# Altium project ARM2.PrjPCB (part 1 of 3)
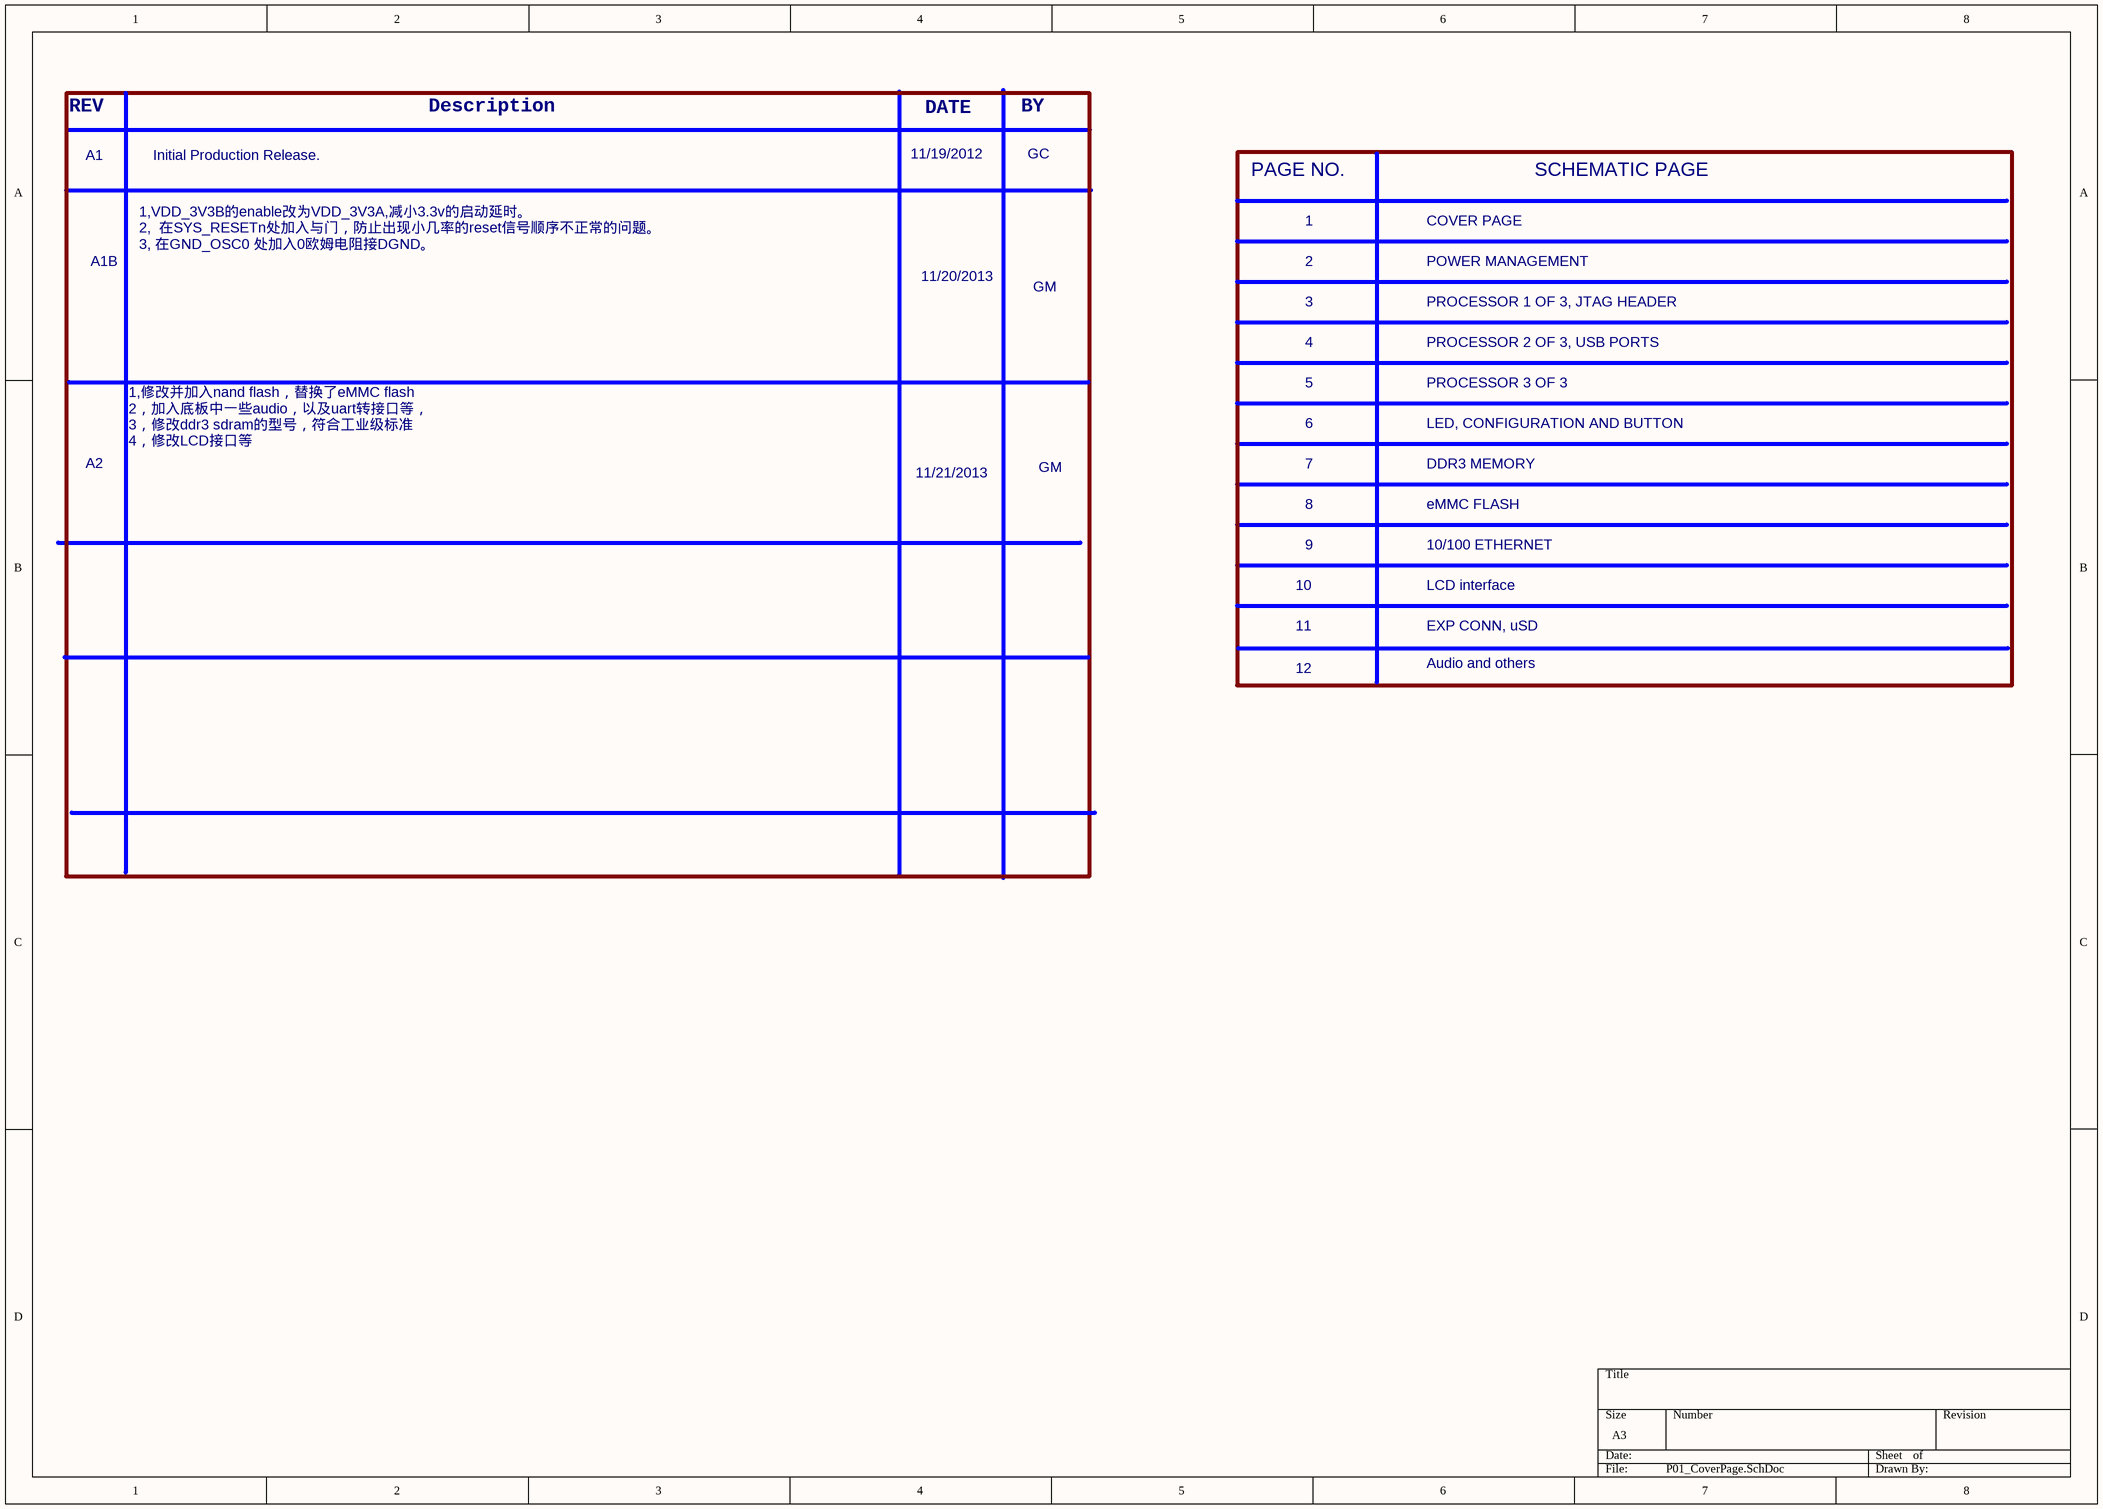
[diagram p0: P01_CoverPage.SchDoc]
12 sheets, 679 parts. Net scope: global (net labels, ports and power ports of the same name join across sheets).
Board file: ARM2.PcbDoc
Sheets:
  P01_CoverPage.SchDoc
  P02_PowerManagement.SchDoc
  P03_Processor1_3.SchDoc
  P04_Processor2_3.SchDoc
  P05_Processor3_3.SchDoc
  P06_LED_BootConfig.SchDoc
  P07_DDR3_SDRAM.SchDoc
  P08_NandFlash.SchDoc
  P09_Ethernet.SchDoc
  P10_LCD.SchDoc
  P11_SDcard.SchDoc
  P12_Exp_Audio.SchDoc

## Sheet P01_CoverPage.SchDoc
size A3

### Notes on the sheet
- REV
- Description
- DATE
- BY
- A1
- Initial Production Release.
- 11/19/2012
- GC
- PAGE NO.
- SCHEMATIC PAGE
- 1
- COVER PAGE
- A1B
- 11/20/2013
- GM
- 3
- 2
- PROCESSOR 1 OF 3, JTAG HEADER
- POWER MANAGEMENT
- 1,VDD_3V3B的enable改为VDD_3V3A,减小3.3v的启动延时。
  2,  在SYS_RESETn处加入与门，防止出现小几率的reset信号顺序不正常的问题。
  3, 在GND_OSC0 处加入0欧姆电阻接DGND。
- 4
- PROCESSOR 2 OF 3, USB PORTS
- 5
- 6
- LED, CONFIGURATION AND BUTTON
- PROCESSOR 3 OF 3
- A2
- 11/21/2013
- 8
- 7
- eMMC FLASH
- DDR3 MEMORY
- 1,修改并加入nand flash，替换了eMMC flash
  2，加入底板中一些audio，以及uart转接口等，
  3，修改ddr3 sdram的型号，符合工业级标准
  4，修改LCD接口等
- 9
- 10/100 ETHERNET
- 10
- 11
- LCD interface
- EXP CONN, uSD
- 12
- Audio and others

## Sheet P02_PowerManagement.SchDoc
size A3
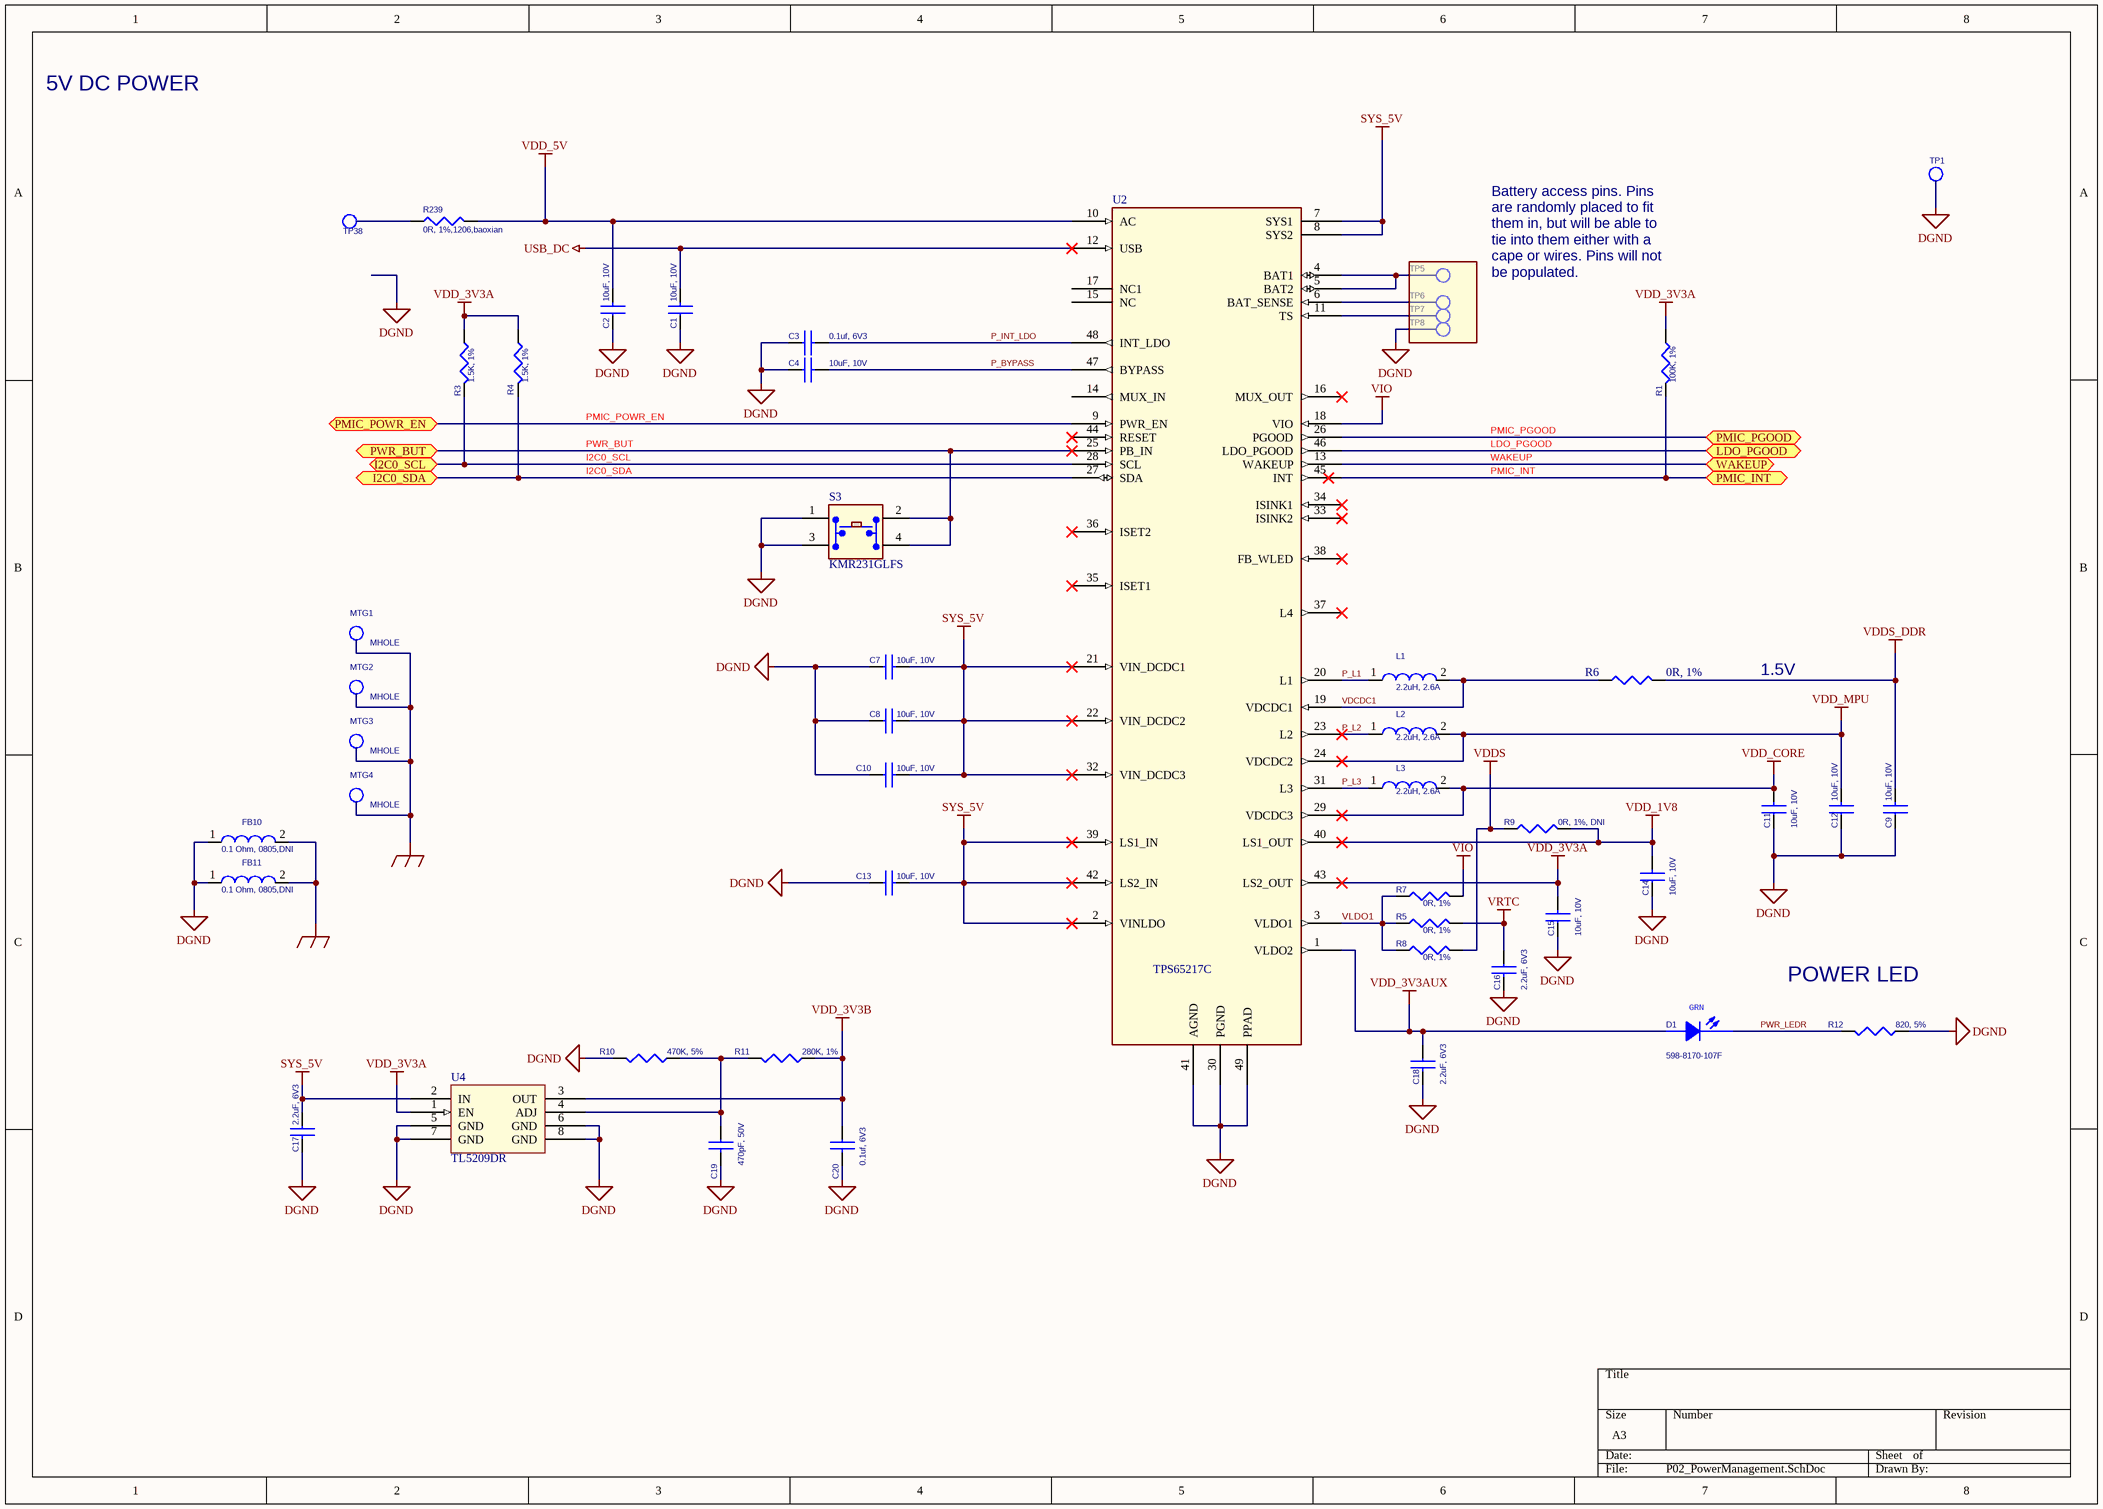
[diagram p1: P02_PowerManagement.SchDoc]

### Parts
C1  10uF, 10V  [805]
C2  10uF, 10V  [805]
C3  0.1uf, 6V3  [402]
C4  10uF, 10V  [805]
C7  10uF, 10V  [805]
C8  10uF, 10V  [805]
C9  10uF, 10V  [805]
C10  10uF, 10V  [805]
C11  10uF, 10V  [805]
C12  10uF, 10V  [805]
C13  10uF, 10V  [805]
C14  10uF, 10V  [805]
C15  10uF, 10V  [805]
C16  2.2uF, 6V3  [0805]
C17  2.2uF, 6V3  [0805]
C18  2.2uF, 6V3  [0805]
C19  470pF, 50V  [402]
C20  0.1uf, 6V3  [402]
D1  598-8170-107F  [LED_0603]
FB10  0.1 Ohm, 0805,DNI  [SM-7351-IND-0805]
FB11  0.1 Ohm, 0805,DNI  [SM-7351-IND-0805]
L1  2.2uH, 2.6A  [2520]
L2  2.2uH, 2.6A  [2520]
L3  2.2uH, 2.6A  [2520]
MTG1  MHOLE  [MTGH200C125D_PL]  (no BOM)
MTG2  MHOLE  [MTGH200C125D_PL]  (no BOM)
MTG3  MHOLE  [MTGH200C125D_PL]  (no BOM)
MTG4  MHOLE  [MTGH200C125D_PL]  (no BOM)
R1  100K, 1%  [R0402]
R3  1.5K, 1%  [R0402]
R4  1.5K, 1%  [R0402]
R5  0R, 1%  [R0402]
R6  0R, 1%  [R0402]
R7  0R, 1%  [R0402]
R8  0R, 1%  [R0402]
R9  0R, 1%, DNI  [R0402]
R10  470K, 5%  [R0402]
R11  280K, 1%  [R0402]
R12  820, 5%  [R0402]
R239  0R, 1%,1206,baoxian  [R1206]
S3  KMR231GLFS  [SW4SMD_63X161LS]
TP1  TESTPT1  [tp1-8040]  (value not drawn)  (no BOM)
TP5  TESTPT1  [TP60C33D]  (value not drawn)  (no BOM)
TP6  TESTPT1  [TP60C33D]  (value not drawn)  (no BOM)
TP7  TESTPT1  [TP60C33D]  (value not drawn)  (no BOM)
TP8  TESTPT1  [TP60C33D]  (value not drawn)  (no BOM)
TP38  TESTPT1  [tp1-8040]  (value not drawn)  (no BOM)
U2  TPS65217C  [U_48_RSL/TPS65217CRSL/RSL]
U4  TL5209DR  [SO8-25X75/TL5209DR/8-SOIC]

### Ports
I2C0_SCL, I2C0_SDA, LDO_PGOOD, PMIC_INT, PMIC_PGOOD, PMIC_POWR_EN, PWR_BUT, WAKEUP

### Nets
DGND: C1.1 C2.1 C3.1 C4.1 C7.1 C8.1 C9.1 C10.1 C11.1 C12.1 C13.1 C14.1 C15.1 C16.2 C17.2 C18.2 C19.2 C20.2 FB10.1 FB11.1 R10.2 R12.1 S3.1(A1) S3.3(A3) TP1.1(TP) TP8.1(TP) U2.30(PGND) U2.41(AGND) U2.49(PPAD) U4.5(GND) U4.6(GND) U4.7(GND) U4.8(GND)
GND_EARTH: FB10.2 FB11.2 MTG1.1(TP) MTG2.1(TP) MTG3.1(TP) MTG4.1(TP)
SYS_5V: C7.2 C8.2 C10.2 C13.2 C17.1 U2.2(VINLDO) U2.7(SYS1) U2.8(SYS2) U2.21(VIN_DCDC1) U2.22(VIN_DCDC2) U2.32(VIN_DCDC3) U2.39(LS1_IN) U2.42(LS2_IN) U4.2(IN)
USB_DC: C1.2 U2.12(USB)
VDD_1V8: C14.2 R9.2 U2.40(LS1_OUT)
VDD_3V3A: C15.2 R1.1 R3.1 R4.1 U2.43(LS2_OUT) U4.1(EN)
VDD_3V3AUX: C18.1 D1.2(A) U2.1(VLDO2)
VDD_3V3B: C20.1 R11.1 U4.3(OUT)
VDD_5V: C2.2 R239.2 U2.10(AC)
VDD_CORE: C11.2 L3.2 U2.29(VDCDC3)
VDD_MPU: C12.2 L2.2 U2.24(VDCDC2)
VDDS: R8.2 R9.1
VDDS_DDR: C9.2 R6.2
VIO: R7.2 U2.18(VIO)
VRTC: C16.1 R5.2
I2C0_SCL: R3.2 U2.28(SCL) ; port I2C0_SCL
I2C0_SDA: R4.2 U2.27(SDA) ; port I2C0_SDA
LDO_PGOOD: U2.46(LDO_PGOOD) ; port LDO_PGOOD
P_BYPASS: C4.2 U2.47(BYPASS)
P_INT_LDO: C3.2 U2.48(INT_LDO)
P_L1: L1.1 U2.20(L1)
P_L2: L2.1 U2.23(L2)
P_L3: L3.1 U2.31(L3)
PMIC_INT: R1.2 U2.45(INT) ; port PMIC_INT
PMIC_PGOOD: U2.26(PGOOD) ; port PMIC_PGOOD
PMIC_POWR_EN: U2.9(PWR_EN) ; port PMIC_POWR_EN
PWR_BUT: S3.2(A2) S3.4 U2.25(PB_IN) ; port PWR_BUT
PWR_LEDR: D1.1(C) R12.2
VDCDC1: L1.2 R6.1 U2.19(VDCDC1)
VLDO1: R5.1 R7.1 R8.1 U2.3(VLDO1)
WAKEUP: U2.13(WAKEUP) ; port WAKEUP
NetC19_1: C19.1 R10.1 R11.2 U4.4(ADJ)
NetR239_1: R239.1 TP38.1(TP)
NetTP5_1: TP5.1(TP) U2.4(BAT1) U2.5(BAT2)
NetTP6_1: TP6.1(TP) U2.6(BAT_SENSE)
NetTP7_1: TP7.1(TP) U2.11(TS)

Not connected (* = marked no-connect by the designer): U2 14(MUX_IN) 15(NC) 16(MUX_OUT)* 17(NC1) 33(ISINK2)* 34(ISINK1)* 35(ISET1)* 36(ISET2)* 37(L4)* 38(FB_WLED)* 44(RESET)*

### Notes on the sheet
- 5V DC POWER
- Battery access pins. Pins are randomly placed to fit them in, but will be able to tie into them either with a cape or wires. Pins will not be populated.
- 1.5V
- (near R12) POWER LED

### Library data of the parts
C1 C2 = CAP_4.7uF_X5R_6.3V_10%_0603: CAP CER 10UF 10V Y5V 0805; Manufacturer: TDK Corporation; Manufacturer Part Number: C2012Y5V1A106Z; Capacitance: 10µF; Tolerance: -20%, +80%; Temperature Coefficient: Y5V (F)
C3 = CAP_10uF_Y5V_10V_10%_0805: CAP CER 0.1UF 6.3V 10% X5R 0402; Manufacturer: TDK Corporation; Manufacturer Part Number: C1005X5R0J104K050BA; Capacitance: 0.1µF; Tolerance: ?0%
C4 C7-C15 = CAP_10uF_Y5V_10V_10%_0805: CAP CER 10UF 10V Y5V 0805; Manufacturer: TDK Corporation; Manufacturer Part Number: C2012Y5V1A106Z; Capacitance: 10µF; Tolerance: -20%, +80%; Temperature Coefficient: Y5V (F)
C16-C18 = CAP_2.2uF_X5R_6.3V_10%_0402: CAP CER 2.2UF 6.3V 10% X5R 0402; Manufacturer: TDK Corporation; Manufacturer Part Number: C1005X5R0J225K050BC; Capacitance: 2.2µF; Tolerance: ?0%
C19 = CAP_2.2uF_X5R_6.3V_10%_0402: CAP CER 470PF 50V 10% X7R 0402; Manufacturer: Murata Electronics North America; Manufacturer Part Number: GRM155R71H471KA01D; Tolerance: ?0%
C20 = CAP_0.1uF_X7R_16V_10% 0402: CAP CER 0.1UF 6.3V 10% X5R 0402; Manufacturer: TDK Corporation; Manufacturer Part Number: C1005X5R0J104K050BA; Capacitance: 0.1µF; Tolerance: ?0%
D1 = LED_LTST-C150GKT: LED GREEN CLEAR 0805 SMD; Manufacturer: Lite-On Inc; Manufacturer Part Number: LTST-C170KGKT; CLASS: DISCRETE; TN: 257-0020-000; Millicandela Rating: 35mcd; Voltage - Forward (Vf) Typ: 2V; Current - Test: 20mA; Wavelength - Dominant: 571nm; Wavelength - Peak: 574nm; Viewing Angle: 130; Lens Style/Size: Rectangle with Flat Top, 1.4mm x 1.25mm
FB10 FB11 = FER_180_200_0: RES .10 OHM 1/8W 5% 0805; Manufacturer: CTS Resistor Products; Manufacturer Part Number: 73L3R10J; Resistance (Ohms): 0.1; Power (Watts): 0.125W, 1/8W; Temperature Coefficient: ?00ppm/°C; Tolerance: ?%
L1 = IND_2.2uH_2.6A_10%_SMD: Inductor 2.2uH smt 2.6A, 58 milliohm; Manufacturer: Murata Electronics North America; Manufacturer Part Number: LQM2HPN2R2MG0L; Inductance: 2.2µH; Current Rating: 1.3A; Tolerance: ?0%; Shielding: Shielded; DC Resistance (DCR): 100 mOhm Max; Frequency - Self Resonant: 40MHz; Frequency - Test: 1MHz
L2 L3 = IND_2.2uH_2.6A_10%_SMD: INDUCTOR 2.2UH 20% 1300MA 1008; PartName: 2.2uH10%2.6Asmd; Mfr: TDK; MfrNum: VLCF5020T-2R2N2R6-3; TIIntPartnumber: 1L0025; Manufacturer: Murata Electronics North America; Manufacturer Part Number: LQM2HPN2R2MG0L; Vendor: Digikey; Cost100: 1.11; Cost10K: 0.37; Inductance: 2.2µH; Current Rating: 1.3A; Tolerance: ?0%; Shielding: Shielded; DC Resistance (DCR): 100 mOhm Max; Frequency - Self Resonant: 40MHz; Frequency - Test: 1MHz
R1 = RES_100K_1/16W_1%_0402: RES 100K OHM 1/16W 1% 0402 SMD; Manufacturer: Stackpole Electronics Inc; Manufacturer Part Number: RMCF0402FT100K; Power (Watts): 0.063W, 1/16W; Temperature Coefficient: ?00ppm/°C; Tolerance: ?%
R3 R4 = RES_1.5K_1/16W_5%_0402: RES 1.50K OHM 1/16W 1% 0402 SMD; Manufacturer: Yageo; Manufacturer Part Number: RC0402FR-071K5L; Power (Watts): 0.063W, 1/16W; Temperature Coefficient: ?00ppm/°C; Tolerance: ?%
R5-R9 = RES_0_1/16W_1%_0402: RES 0.0 OHM 1/16W 0402 SMD; Manufacturer: Yageo; Manufacturer Part Number: RC0402JR-070RL; Power (Watts): 0.063W, 1/16W; Resistance (Ohms): 0.0; Tolerance: Jumper
R10 R239 = RES_470_1/10W_5%_0402: RES 470K OHM 1/16W 1% 0402 SMD; Manufacturer: Yageo; Manufacturer Part Number: RC0402FR-07470KL; Power (Watts): 0.063W, 1/16W; Temperature Coefficient: ?00ppm/°C; Tolerance: ?%
R11 = RES_470_1/10W_5%_0402: RES 280K OHM 1/16W 1% 0402 SMD; Manufacturer: Stackpole Electronics Inc; Manufacturer Part Number: RMCF0402FT280K; Power (Watts): 0.063W, 1/16W; Temperature Coefficient: ?00ppm/°C; Tolerance: ?%
R12 = RES_470_1/10W_5%_0402: RES 820 OHM 1/10W 5% 0402 SMD; Manufacturer: Yageo; Manufacturer Part Number: RC0402JR-07820RL; Description: RES 820 OHM 1/16W 5% 0402 SMD; Resistance (Ohms): 820; Power (Watts): 0.063W, 1/16W; Temperature Coefficient: ?00ppm/°C; Tolerance: ?%
S3 = KMR2: Microminiature Tact Switch for SMT; Manufacturer: C&K Components; Circuit: SPST-NO; Switch Function: Off-Mom; Contact Rating @ Voltage: 0.05A @ 32VDC; Actuator Type: Standard; Actuator Height off PCB, from Pins: 1.90mm; Actuator Orientation: Top Actuated; Outline: 4.60mm x 2.80mm; Illumination: Non-Illuminated; Operating Force: 300gf; Switch Travel: 0.25mm; Mechanical Life: 150,000 Cycles
U2 = PWR_TPS65217_2: IC PMIC BATT PWR SYST 48VQFN; Manufacturer: Texas Instruments; Manufacturer Part Number: TPS65217CRSLR; Voltage - Supply: 2.75 V ~ 5.8 V
U4 = TL5209: IC LDO VOLT REG 500MA 8-SOIC; Manufacturer: Texas Instruments; Regulator Topology: Positive Adjustable; Voltage - Output: 2.5 V ~ 6.5 V; Voltage - Input: 2.5 V ~ 16 V; Voltage - Dropout (Typical): 0.35V @ 500mA; Number of Regulators: 1; Current - Output: 500mA (Max)

## Sheet P03_Processor1_3.SchDoc
size A2
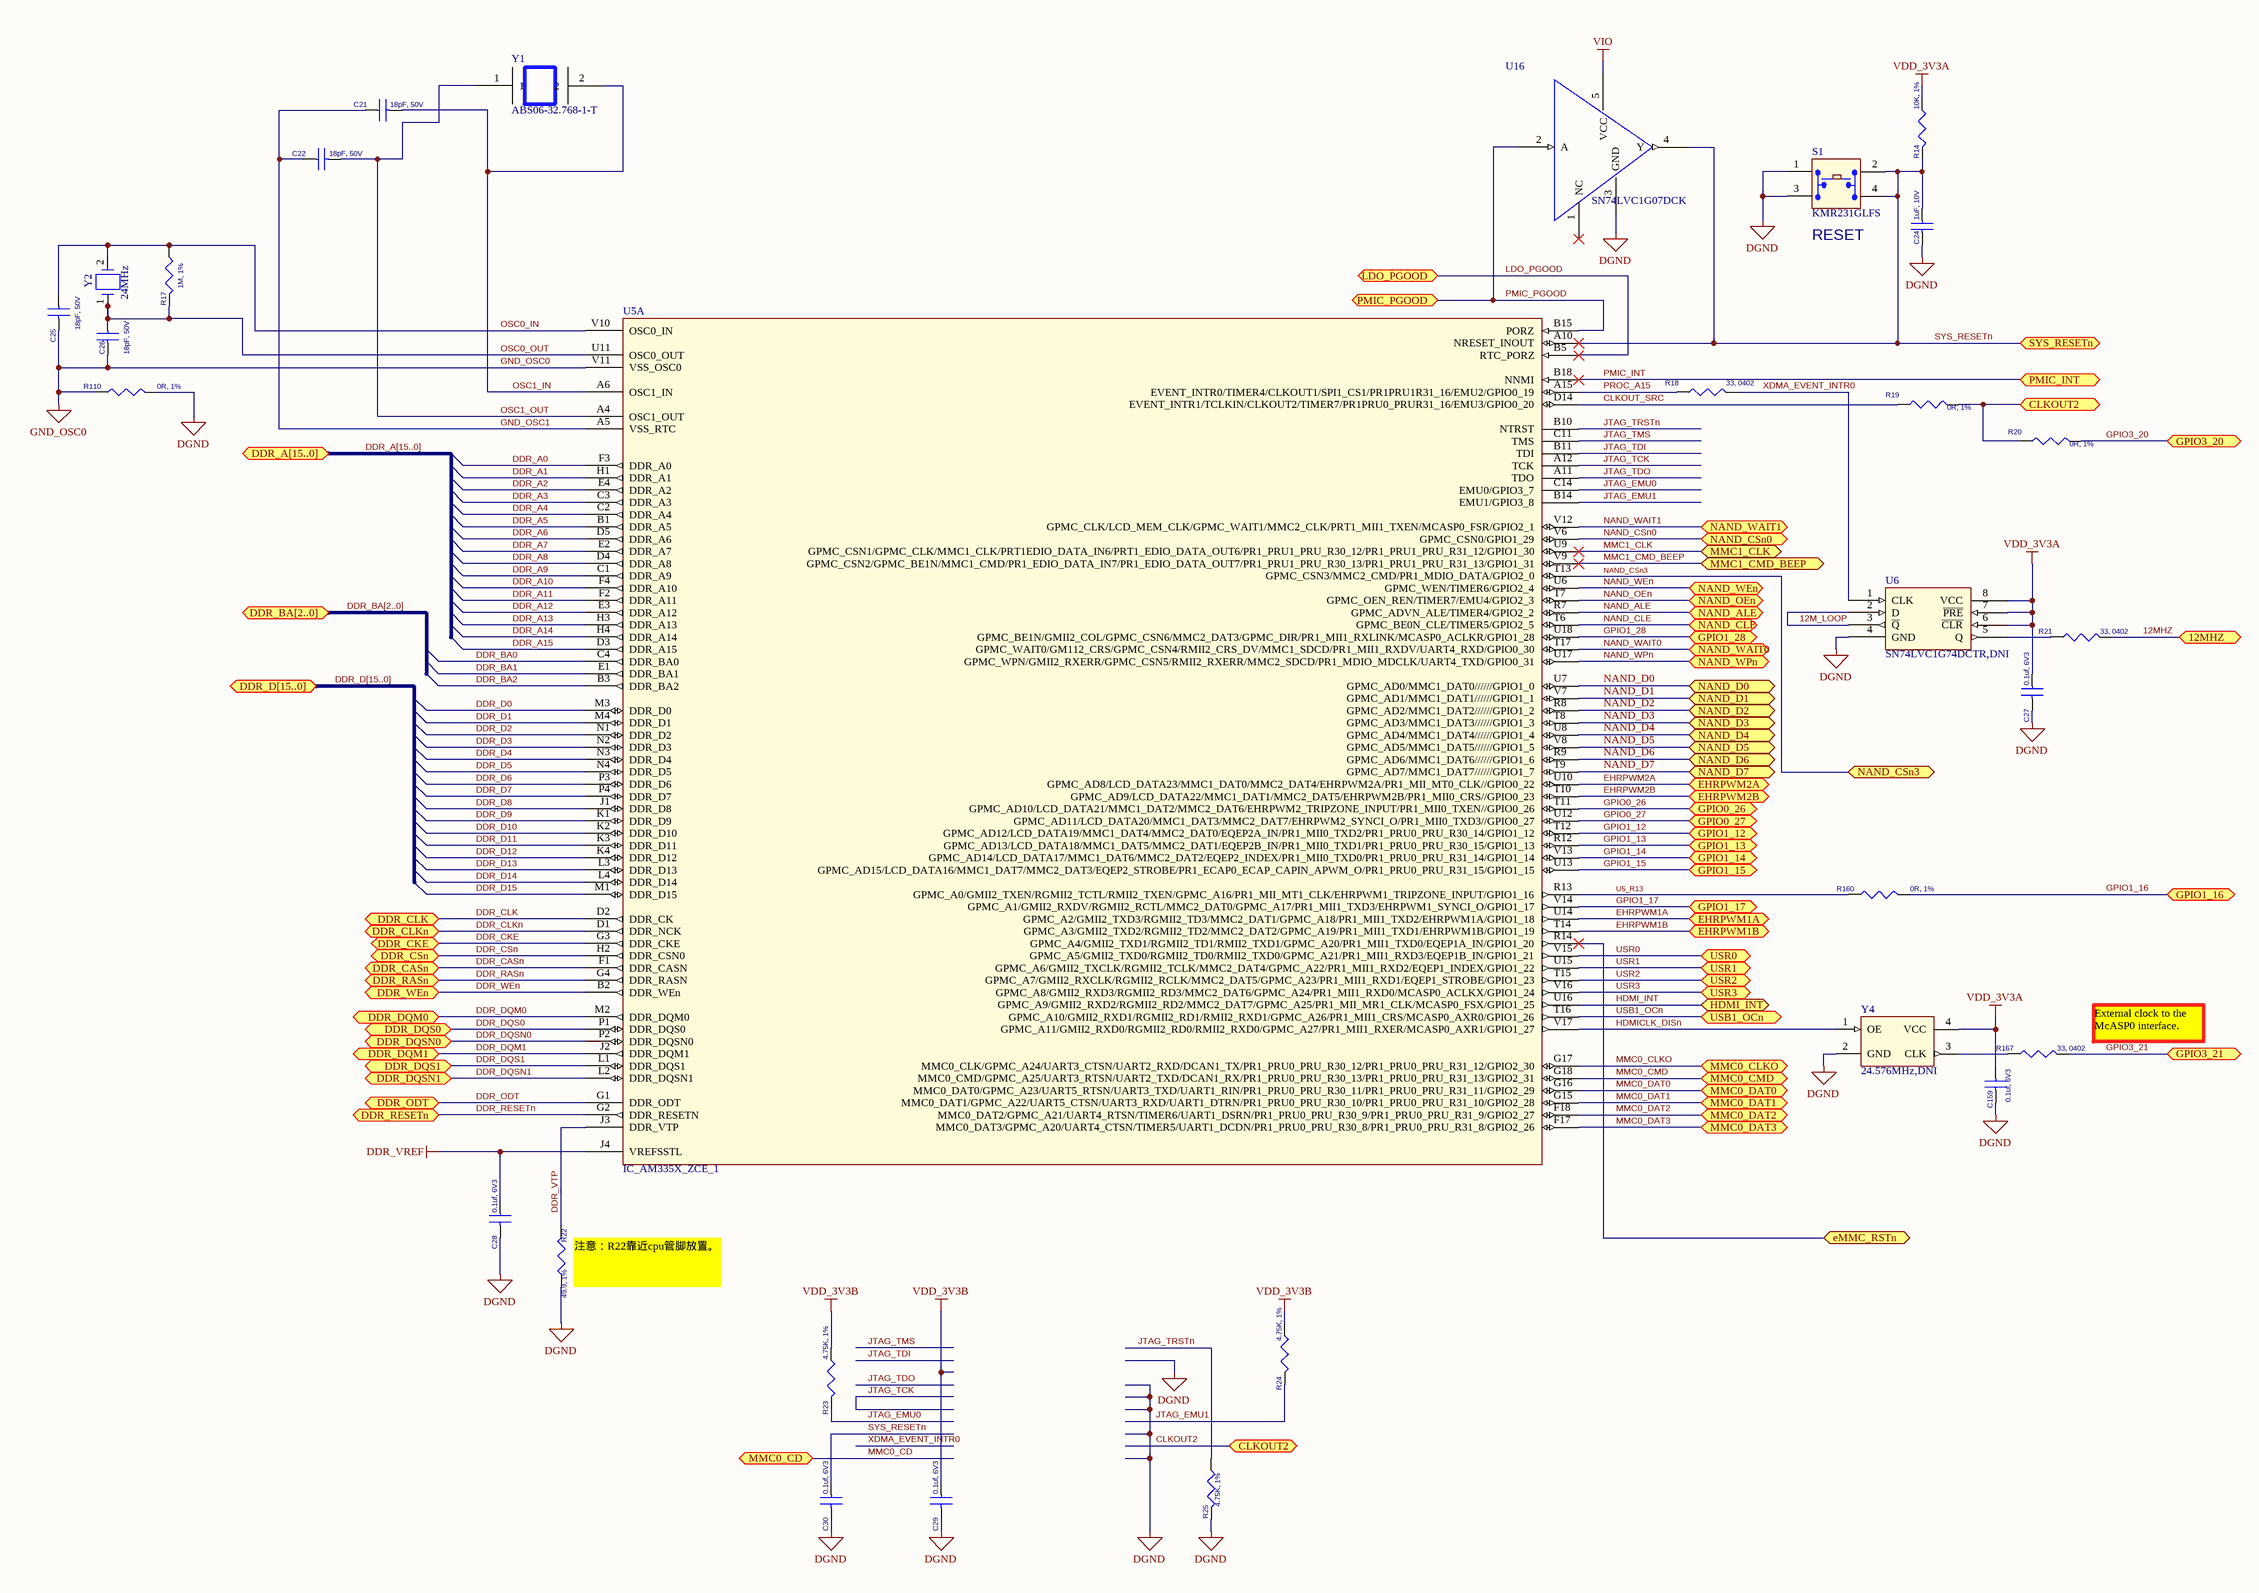
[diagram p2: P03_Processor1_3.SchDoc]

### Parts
C21  18pF, 50V  [402]
C22  18pF, 50V  [402]
C24  1uF, 10V  [402]
C25  18pF, 50V  [402]
C26  18pF, 50V  [402]
C27  0.1uf, 6V3  [402]
C28  0.1uf, 6V3  [402]
C29  0.1uf, 6V3  [402]
C30  0.1uf, 6V3  [402]
C159  0.1uf, 6V3  [402]
R14  10K, 1%  [R0402]
R17  1M, 1%  [R0402]
R18  33, 0402  [R0402]
R19  0R, 1%  [R0402]
R20  0R, 1%  [R0402]
R21  33, 0402  [R0402]
R22  49.9, 1%  [R0402]
R23  4.75K, 1%  [R0402]
R24  4.75K, 1%  [R0402]
R25  4.75K, 1%  [R0402]
R110  0R, 1%  [R0402]
R160  0R, 1%  [R0402]
R167  33, 0402  [R0402]
S1  KMR231GLFS  [SW4SMD_63X161LS]
U5  IC_AM335X_ZCE_1  [am33xx_15x15/AM3354ZCZD72/324-NFBGA]  (part A of 3)
U6  SN74LVC1G74DCTR,DNI  [SOP8_DCT/SN74LVC1G74DCTR/SSOP-DCT]
U16  SN74LVC1G07DCK  [SN74LVC1G07DCK/SOT-DCK]
Y1  ABS06-32.768-1-T  [SMD/ABS06-32.768KHZ-1-T]
Y2  24MHz  [XTAL150SMD_125X196]
Y4  24.576MHz,DNI  [OSC4_61X65LS_79X98SMD]

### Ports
12MHZ, CLKOUT2, DDR_A[15..0], DDR_BA[2..0], DDR_CASn, DDR_CKE, DDR_CLK, DDR_CLKn, DDR_CSn, DDR_D[15..0], DDR_DQM0, DDR_DQM1, DDR_DQS0, DDR_DQS1, DDR_DQSN0, DDR_DQSN1, DDR_ODT, DDR_RASn, DDR_RESETn, DDR_WEn, EHRPWM1A, EHRPWM1B, EHRPWM2A, EHRPWM2B, eMMC_RSTn (bidir), GPIO0_26, GPIO0_27, GPIO1_12, GPIO1_13, GPIO1_14, GPIO1_15, GPIO1_16, GPIO1_17, GPIO1_28, GPIO3_20, GPIO3_21, HDMI_INT, LDO_PGOOD, MMC0_CD, MMC0_CLKO, MMC0_CMD, MMC0_DAT0, MMC0_DAT1, MMC0_DAT2, MMC0_DAT3, MMC1_CLK, MMC1_CMD_BEEP, NAND_ALE, NAND_CLE, NAND_CSn0, NAND_CSn3 (bidir), NAND_D0, NAND_D1 (bidir), NAND_D2, NAND_D3, NAND_D4, NAND_D5, NAND_D6, NAND_D7, NAND_OEn, NAND_WAIT0, NAND_WAIT1, NAND_WEn, NAND_WPn, PMIC_INT, PMIC_PGOOD, SYS_RESETn, USB1_OCn, USR0, USR1, USR2, USR3

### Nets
DDR_VREF: C28.1 U5.J4(VREFSSTL)
DGND: C24.2 C27.2 C28.2 C29.2 C30.2 C159.2 R22.1 R25.2 R110.2 S1.1(A1) S1.3(A3) U6.4(GND) U16.3(GND) Y4.2(GND)
GND_OSC0: C25.2 C26.2 R110.1 U5.V11(VSS_OSC0)
VDD_3V3A: C27.1 C159.1 R14.1 U6.6(~{CLR}) U6.7(~{PRE}) U6.8(VCC) Y4.4(VCC)
VDD_3V3B: C29.1 R23.1 R24.1
VIO: U16.5(VCC)
12M_LOOP: U6.2(D) U6.3(~{Q})
12MHZ: R21.2 ; port 12MHZ
CLKOUT2: R19.2 R20.1 ; port CLKOUT2
CLKOUT_SRC: R19.1 U5.D14(EVENT_INTR1/TCLKIN/CLKOUT2/TIMER7/PR1PRU0_PRUR31_16/EMU3/GPIO0_20)
DDR_A0: U5.F3(DDR_A0)
DDR_A1: U5.H1(DDR_A1)
DDR_A2: U5.E4(DDR_A2)
DDR_A3: U5.C3(DDR_A3)
DDR_A4: U5.C2(DDR_A4)
DDR_A5: U5.B1(DDR_A5)
DDR_A6: U5.D5(DDR_A6)
DDR_A7: U5.E2(DDR_A7)
DDR_A8: U5.D4(DDR_A8)
DDR_A9: U5.C1(DDR_A9)
DDR_A10: U5.F4(DDR_A10)
DDR_A11: U5.F2(DDR_A11)
DDR_A12: U5.E3(DDR_A12)
DDR_A13: U5.H3(DDR_A13)
DDR_A14: U5.H4(DDR_A14)
DDR_A15: U5.D3(DDR_A15)
DDR_BA0: U5.C4(DDR_BA0)
DDR_BA1: U5.E1(DDR_BA1)
DDR_BA2: U5.B3(DDR_BA2)
DDR_CASn: U5.F1(DDR_CASN) ; port DDR_CASn
DDR_CKE: U5.G3(DDR_CKE) ; port DDR_CKE
DDR_CLK: U5.D2(DDR_CK) ; port DDR_CLK
DDR_CLKn: U5.D1(DDR_NCK) ; port DDR_CLKn
DDR_CSn: U5.H2(DDR_CSN0) ; port DDR_CSn
DDR_D0: U5.M3(DDR_D0)
DDR_D1: U5.M4(DDR_D1)
DDR_D2: U5.N1(DDR_D2)
DDR_D3: U5.N2(DDR_D3)
DDR_D4: U5.N3(DDR_D4)
DDR_D5: U5.N4(DDR_D5)
DDR_D6: U5.P3(DDR_D6)
DDR_D7: U5.P4(DDR_D7)
DDR_D8: U5.J1(DDR_D8)
DDR_D9: U5.K1(DDR_D9)
DDR_D10: U5.K2(DDR_D10)
DDR_D11: U5.K3(DDR_D11)
DDR_D12: U5.K4(DDR_D12)
DDR_D13: U5.L3(DDR_D13)
DDR_D14: U5.L4(DDR_D14)
DDR_D15: U5.M1(DDR_D15)
DDR_DQM0: U5.M2(DDR_DQM0) ; port DDR_DQM0
DDR_DQM1: U5.J2(DDR_DQM1) ; port DDR_DQM1
DDR_DQS0: U5.P1(DDR_DQS0) ; port DDR_DQS0
DDR_DQS1: U5.L1(DDR_DQS1) ; port DDR_DQS1
DDR_DQSN0: U5.P2(DDR_DQSN0) ; port DDR_DQSN0
DDR_DQSN1: U5.L2(DDR_DQSN1) ; port DDR_DQSN1
DDR_ODT: U5.G1(DDR_ODT) ; port DDR_ODT
DDR_RASn: U5.G4(DDR_RASN) ; port DDR_RASn
DDR_RESETn: U5.G2(DDR_RESETN) ; port DDR_RESETn
DDR_VTP: R22.2 U5.J3(DDR_VTP)
DDR_WEn: U5.B2(DDR_WEn) ; port DDR_WEn
EHRPWM1A: U5.U14(GPMC_A2/GMII2_TXD3/RGMII2_TD3/MMC2_DAT1/GPMC_A18/PR1_MII1_TXD2/EHRPWM1A/GPIO1_18) ; port EHRPWM1A
EHRPWM1B: U5.T14(GPMC_A3/GMII2_TXD2/RGMII2_TD2/MMC2_DAT2/GPMC_A19/PR1_MII1_TXD1/EHRPWM1B/GPIO1_19) ; port EHRPWM1B
EHRPWM2A: U5.U10(GPMC_AD8/LCD_DATA23/MMC1_DAT0/MMC2_DAT4/EHRPWM2A/PR1_MII_MT0_CLK//GPIO0_22) ; port EHRPWM2A
EHRPWM2B: U5.T10(GPMC_AD9/LCD_DATA22/MMC1_DAT1/MMC2_DAT5/EHRPWM2B/PR1_MII0_CRS//GPIO0_23) ; port EHRPWM2B
GND_OSC1: C21.1 C22.1 U5.A5(VSS_RTC)
GPIO0_26: U5.T11(GPMC_AD10/LCD_DATA21/MMC1_DAT2/MMC2_DAT6/EHRPWM2_TRIPZONE_INPUT/PR1_MII0_TXEN//GPIO0_26) ; port GPIO0_26
GPIO0_27: U5.U12(GPMC_AD11/LCD_DATA20/MMC1_DAT3/MMC2_DAT7/EHRPWM2_SYNCI_O/PR1_MII0_TXD3//GPIO0_27) ; port GPIO0_27
GPIO1_12: U5.T12(GPMC_AD12/LCD_DATA19/MMC1_DAT4/MMC2_DAT0/EQEP2A_IN/PR1_MII0_TXD2/PR1_PRU0_PRU_R30_14/GPIO1_12) ; port GPIO1_12
GPIO1_13: U5.R12(GPMC_AD13/LCD_DATA18/MMC1_DAT5/MMC2_DAT1/EQEP2B_IN/PR1_MII0_TXD1/PR1_PRU0_PRU_R30_15/GPIO1_13) ; port GPIO1_13
GPIO1_14: U5.V13(GPMC_AD14/LCD_DATA17/MMC1_DAT6/MMC2_DAT2/EQEP2_INDEX/PR1_MII0_TXD0/PR1_PRU0_PRU_R31_14/GPIO1_14) ; port GPIO1_14
GPIO1_15: U5.U13(GPMC_AD15/LCD_DATA16/MMC1_DAT7/MMC2_DAT3/EQEP2_STROBE/PR1_ECAP0_ECAP_CAPIN_APWM_O/PR1_PRU0_PRU_R31_15/GPIO1_15) ; port GPIO1_15
GPIO1_16: R160.2 ; port GPIO1_16
GPIO1_17: U5.V14(GPMC_A1/GMII2_RXDV/RGMII2_RCTL/MMC2_DAT0/GPMC_A17/PR1_MII1_TXD3/EHRPWM1_SYNCI_O/GPIO1_17) ; port GPIO1_17
GPIO1_28: U5.U18(GPMC_BE1N/GMII2_COL/GPMC_CSN6/MMC2_DAT3/GPMC_DIR/PR1_MII1_RXLINK/MCASP0_ACLKR/GPIO1_28) ; port GPIO1_28
GPIO3_20: R20.2 ; port GPIO3_20
GPIO3_21: R167.2 ; port GPIO3_21
HDMI_INT: U5.U16(GPMC_A9/GMII2_RXD2/RGMII2_RD2/MMC2_DAT7/GPMC_A25/PR1_MII_MR1_CLK/MCASP0_FSX/GPIO1_25) ; port HDMI_INT
HDMICLK_DISn: U5.V17(GPMC_A11/GMII2_RXD0/RGMII2_RD0/RMII2_RXD0/GPMC_A27/PR1_MII1_RXER/MCASP0_AXR1/GPIO1_27) Y4.1(OE)
JTAG_EMU0: R23.2 U5.C14(EMU0/GPIO3_7)
JTAG_EMU1: R24.2 U5.B14(EMU1/GPIO3_8)
JTAG_TCK: U5.A12(TCK)
JTAG_TDI: U5.B11(TDI)
JTAG_TDO: U5.A11(TDO)
JTAG_TMS: U5.C11(TMS)
JTAG_TRSTn: R25.1 U5.B10(NTRST)
LDO_PGOOD: U5.B5(RTC_PORZ) ; port LDO_PGOOD
MMC0_CLKO: U5.G17(MMC0_CLK/GPMC_A24/UART3_CTSN/UART2_RXD/DCAN1_TX/PR1_PRU0_PRU_R30_12/PR1_PRU0_PRU_R31_12/GPIO2_30) ; port MMC0_CLKO
MMC0_CMD: U5.G18(MMC0_CMD/GPMC_A25/UART3_RTSN/UART2_TXD/DCAN1_RX/PR1_PRU0_PRU_R30_13/PR1_PRU0_PRU_R31_13/GPIO2_31) ; port MMC0_CMD
MMC0_DAT0: U5.G16(MMC0_DAT0/GPMC_A23/UART5_RTSN/UART3_TXD/UART1_RIN/PR1_PRU0_PRU_R30_11/PR1_PRU0_PRU_R31_11/GPIO2_29) ; port MMC0_DAT0
MMC0_DAT1: U5.G15(MMC0_DAT1/GPMC_A22/UART5_CTSN/UART3_RXD/UART1_DTRN/PR1_PRU0_PRU_R30_10/PR1_PRU0_PRU_R31_10/GPIO2_28) ; port MMC0_DAT1
MMC0_DAT2: U5.F18(MMC0_DAT2/GPMC_A21/UART4_RTSN/TIMER6/UART1_DSRN/PR1_PRU0_PRU_R30_9/PR1_PRU0_PRU_R31_9/GPIO2_27) ; port MMC0_DAT2
MMC0_DAT3: U5.F17(MMC0_DAT3/GPMC_A20/UART4_CTSN/TIMER5/UART1_DCDN/PR1_PRU0_PRU_R30_8/PR1_PRU0_PRU_R31_8/GPIO2_26) ; port MMC0_DAT3
MMC1_CLK: U5.U9(GPMC_CSN1/GPMC_CLK/MMC1_CLK/PRT1EDIO_DATA_IN6/PRT1_EDIO_DATA_OUT6/PR1_PRU1_PRU_R30_12/PR1_PRU1_PRU_R31_12/GPIO1_30) ; port MMC1_CLK
MMC1_CMD_BEEP: U5.V9(GPMC_CSN2/GPMC_BE1N/MMC1_CMD/PR1_EDIO_DATA_IN7/PR1_EDIO_DATA_OUT7/PR1_PRU1_PRU_R30_13/PR1_PRU1_PRU_R31_13/GPIO1_31) ; port MMC1_CMD_BEEP
NAND_ALE: U5.R7(GPMC_ADVN_ALE/TIMER4/GPIO2_2) ; port NAND_ALE
NAND_CLE: U5.T6(GPMC_BE0N_CLE/TIMER5/GPIO2_5) ; port NAND_CLE
NAND_CSn0: U5.V6(GPMC_CSN0/GPIO1_29) ; port NAND_CSn0
NAND_CSn3: U5.T13(GPMC_CSN3/MMC2_CMD/PR1_MDIO_DATA/GPIO2_0) ; port NAND_CSn3
NAND_D0: U5.U7(GPMC_AD0/MMC1_DAT0//////GPIO1_0) ; port NAND_D0
NAND_D1: U5.V7(GPMC_AD1/MMC1_DAT1//////GPIO1_1) ; port NAND_D1
NAND_D2: U5.R8(GPMC_AD2/MMC1_DAT2//////GPIO1_2) ; port NAND_D2
NAND_D3: U5.T8(GPMC_AD3/MMC1_DAT3//////GPIO1_3) ; port NAND_D3
NAND_D4: U5.U8(GPMC_AD4/MMC1_DAT4//////GPIO1_4) ; port NAND_D4
NAND_D5: U5.V8(GPMC_AD5/MMC1_DAT5//////GPIO1_5) ; port NAND_D5
NAND_D6: U5.R9(GPMC_AD6/MMC1_DAT6//////GPIO1_6) ; port NAND_D6
NAND_D7: U5.T9(GPMC_AD7/MMC1_DAT7//////GPIO1_7) ; port NAND_D7
NAND_OEn: U5.T7(GPMC_OEN_REN/TIMER7/EMU4/GPIO2_3) ; port NAND_OEn
NAND_WAIT0: U5.T17(GPMC_WAIT0/GM112_CRS/GPMC_CSN4/RMII2_CRS_DV/MMC1_SDCD/PR1_MII1_RXDV/UART4_RXD/GPIO0_30) ; port NAND_WAIT0
NAND_WAIT1: U5.V12(GPMC_CLK/LCD_MEM_CLK/GPMC_WAIT1/MMC2_CLK/PRT1_MII1_TXEN/MCASP0_FSR/GPIO2_1) ; port NAND_WAIT1
NAND_WEn: U5.U6(GPMC_WEN/TIMER6/GPIO2_4) ; port NAND_WEn
NAND_WPn: U5.U17(GPMC_WPN/GMII2_RXERR/GPMC_CSN5/RMII2_RXERR/MMC2_SDCD/PR1_MDIO_MDCLK/UART4_TXD/GPIO0_31) ; port NAND_WPn
OSC0_IN: C25.1 R17.1 U5.V10(OSC0_IN) Y2.2
OSC0_OUT: C26.1 R17.2 U5.U11(OSC0_OUT) Y2.1
OSC1_IN: C21.2 U5.A6(OSC1_IN) Y1.2
OSC1_OUT: C22.2 U5.A4(OSC1_OUT) Y1.1
PMIC_INT: U5.B18(NNMI) ; port PMIC_INT
PMIC_PGOOD: U5.B15(PORZ) U16.2(A) ; port PMIC_PGOOD
PROC_A15: R18.1 U5.A15(EVENT_INTR0/TIMER4/CLKOUT1/SPI1_CS1/PR1PRU1R31_16/EMU2/GPIO0_19)
SYS_RESETn: C24.1 C30.1 R14.2 S1.2(A2) S1.4 U5.A10(NRESET_INOUT) U16.4(Y) ; port SYS_RESETn
U5_R13: R160.1 U5.R13(GPMC_A0/GMII2_TXEN/RGMII2_TCTL/RMII2_TXEN/GPMC_A16/PR1_MII_MT1_CLK/EHRPWM1_TRIPZONE_INPUT/GPIO1_16)
USB1_OCn: U5.T16(GPMC_A10/GMII2_RXD1/RGMII2_RD1/RMII2_RXD1/GPMC_A26/PR1_MII1_CRS/MCASP0_AXR0/GPIO1_26) ; port USB1_OCn
USR0: U5.V15(GPMC_A5/GMII2_TXD0/RGMII2_TD0/RMII2_TXD0/GPMC_A21/PR1_MII1_RXD3/EQEP1B_IN/GPIO1_21) ; port USR0
USR1: U5.U15(GPMC_A6/GMII2_TXCLK/RGMII2_TCLK/MMC2_DAT4/GPMC_A22/PR1_MII1_RXD2/EQEP1_INDEX/GPIO1_22) ; port USR1
USR2: U5.T15(GPMC_A7/GMII2_RXCLK/RGMII2_RCLK/MMC2_DAT5/GPMC_A23/PR1_MII1_RXD1/EQEP1_STROBE/GPIO1_23) ; port USR2
USR3: U5.V16(GPMC_A8/GMII2_RXD3/RGMII2_RD3/MMC2_DAT6/GPMC_A24/PR1_MII1_RXD0/MCASP0_ACLKX/GPIO1_24) ; port USR3
XDMA_EVENT_INTR0: R18.2 U6.1(CLK)
NetR21_1: R21.1 U6.5(Q)
NetR167_1: R167.1 Y4.3(CLK)
NetU5_R14: U5.R14(GPMC_A4/GMII2_TXD1/RGMII2_TD1/RMII2_TXD1/GPMC_A20/PR1_MII1_TXD0/EQEP1A_IN/GPIO1_20) ; port eMMC_RSTn

Not connected (* = marked no-connect by the designer): U16 1(NC)*

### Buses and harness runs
bus DDR_A[15..0] = port DDR_A[15..0]
bus DDR_BA[2..0] = port DDR_BA[2..0]
bus DDR_D[15..0] = port DDR_D[15..0]

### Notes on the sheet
- (near S1) RESET
- (near R167) External clock to the
  McASP0 interface.
- (near R22) 注意：R22靠近cpu管脚放置。

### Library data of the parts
C21 C22 C25 C26 = CAP_18PF_COG_50V_5%_0402: CAP CER 18PF 50V 5% NP0 0402; Manufacturer: TDK Corporation; Manufacturer Part Number: C1005C0G1H180J050BA; Tolerance: ?%; Temperature Coefficient: C0G, NP0
C24 = CAP_1.0UF_X5R_10V_10%_0402: CAP CER 1UF 10V 10% X5R 0402; Manufacturer: AVX Corporation; Manufacturer Part Number: 0402ZD105KAT2A; Capacitance: 1.0µF; Tolerance: ?0%
C27-C30 C159 = CAP_0.1uF_X7R_16V_10% 0402: as C20 on sheet P02_PowerManagement
R14 = RES_10K_1/16W_1%_0402: RES 10K OHM 1/16W 5% 0402 SMD; Manufacturer: Rohm Semiconductor; Manufacturer Part Number: MCR01MZPJ103; Power (Watts): 0.063W, 1/16W; Temperature Coefficient: ?00ppm/°C; Tolerance: ?%
R17 = RES_1M_1/16W_1%_0402: Resistor 1Mohm 1/16W 1% 0402; Manufacturer: Stackpole Electronics Inc; Manufacturer Part Number: RMCF0402FT1M00; Power (Watts): 0.063W, 1/16W; Temperature Coefficient: ?00ppm/°C; Tolerance: ?%
R18 R21 R167 = RES_33_0402: RES 33 OHM 1/16W 5% 0402 SMD; Manufacturer: Panasonic Electronic Components; Manufacturer Part Number: ERJ-2GEJ330X; Resistance (Ohms): 33; Power (Watts): 0.1W, 1/10W; Temperature Coefficient: ?00ppm/°C; Tolerance: ?%
R19 R20 R110 R160 = RES_0_1/16W_1%_0402: RES 0.0 OHM 1/16W 0402 SMD; Manufacturer: Yageo; Manufacturer Part Number: RC0402JR-070RL; Resistance (Ohms): 0.0; Power (Watts): 0.063W, 1/16W; Tolerance: Jumper
R22 = RES_4.7K_0402: RES 49.9 OHM 1/16W 1% 0402 SMD; Manufacturer: Yageo; Manufacturer Part Number: RC0402FR-0749R9L; Resistance (Ohms): 49.9; Power (Watts): 0.063W, 1/16W; Temperature Coefficient: ?00ppm/°C; Tolerance: ?%
R23-R25 = RES_4.7K_0402: RES 4.75K 1/16W 1% 0402 SMD; Manufacturer: Stackpole Electronics Inc; Manufacturer Part Number: RMCF0402FT4K75; Power (Watts): 0.063W, 1/16W; Temperature Coefficient: ?00ppm/°C; Tolerance: ?%
S1 = KMR2: as S3 on sheet P02_PowerManagement
U5 = IC_AM335X_ZCE_1: SubArctic Cortex A8 Processor 15x15; Manufacturer: Texas Instruments; Manufacturer Part Number: XAM3359ZCZ; Processor Type: ARM Microprocessor; Voltage: 1.06 V ~ 1.15 V
U6 = SN74LVC1G74DCTR: SINGLE  POSITIVE-EDGE-TRIGGERED  D-TYPE  FLIP-FLOP WITH  CLEAR  AND  PRESET; Manufacturer: Texas Instruments; Function: Set(Preset) and Reset; Output Type: Differential; Number of Elements: 1; Frequency - Clock: 200MHz; Delay Time - Propagation: 1.6ns; Trigger Type: Positive Edge; Current - Output High, Low: 32mA, 32mA; Voltage - Supply: 1.65 V ~ 5.5 V
Y2 = CRYS_24MHz_SCC: CRYSTAL 24.000MHZ 18PF SMD; Manufacturer: TXC CORPORATION; Manufacturer Part Number: 7A-24.000MAAJ-T; Frequency Stability: ?0ppm; ESR (Equivalent Series Resistance): 50 Ohm; Operating Mode: Fundamental
Y4 = ASDMB: Manufacturer: Abracon Corporation; Manufacturer Part Number: ASDMB-24.576MHZ-LC-T; Function: Standby (Power Down); Output: CMOS; Voltage - Supply: 1.8 V ~ 3.3 V; Frequency Stability: ?0ppm; Current - Supply (Max): 16mA; Current - Supply (Disable) (Max): 15µA

## Sheet P04_Processor2_3.SchDoc
size A2
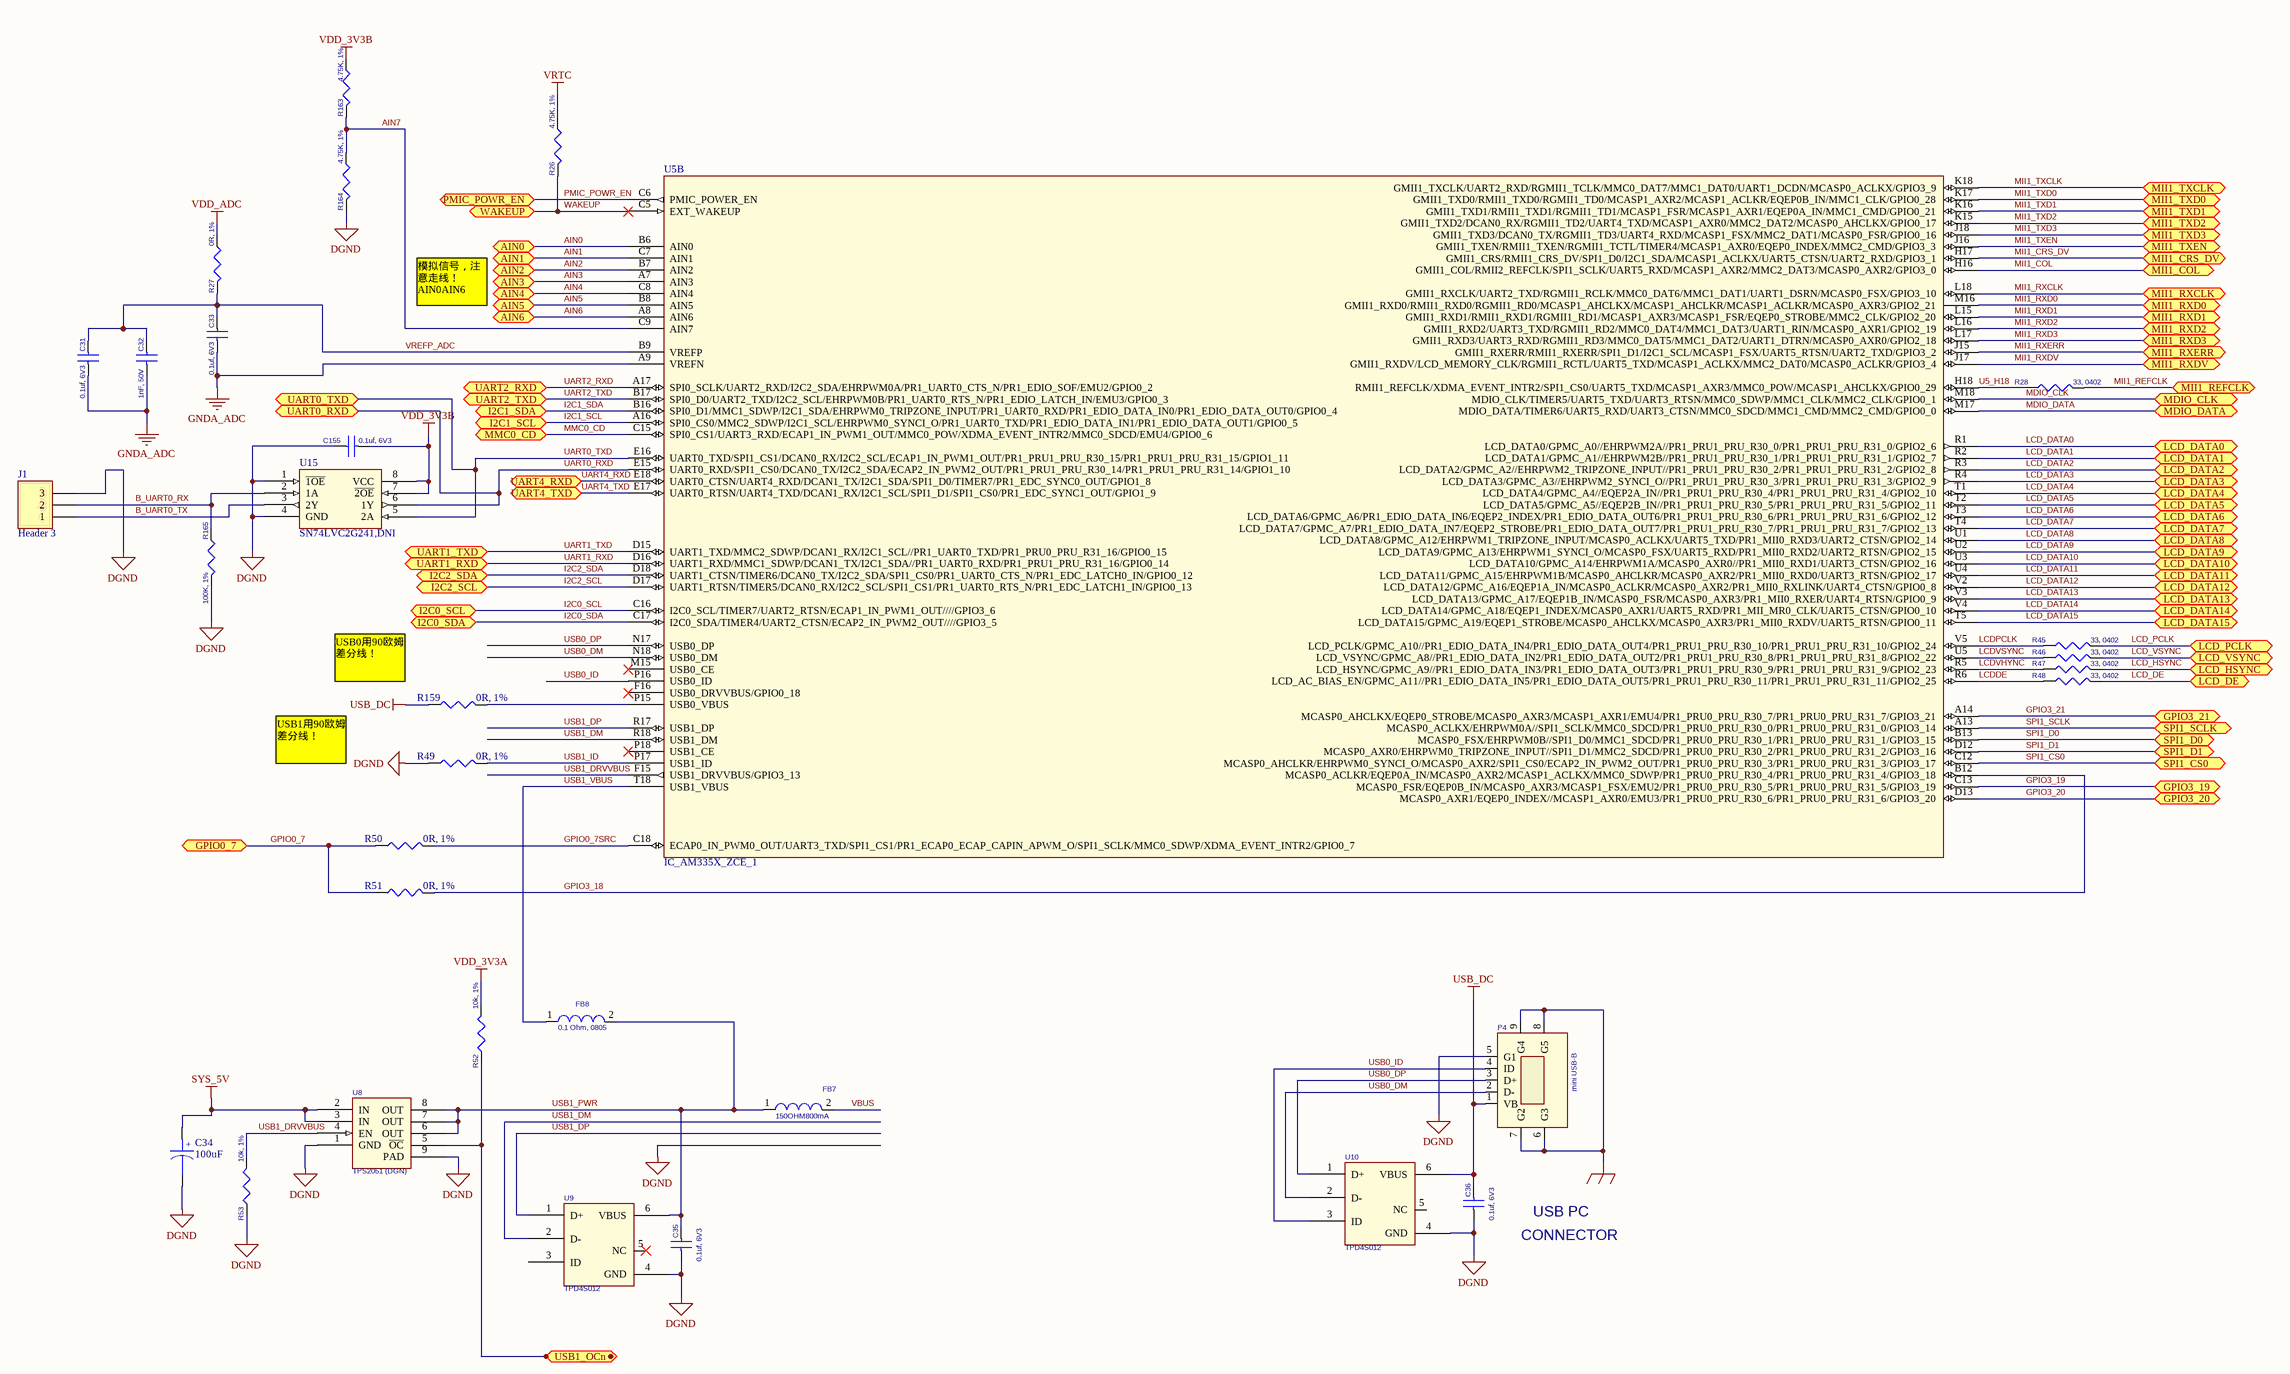
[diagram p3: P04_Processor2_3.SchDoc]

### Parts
C31  0.1uf, 6V3  [402]
C32  1nF, 50V  [402]
C33  0.1uf, 6V3  [402]
C34  100uF  [7343T]
C35  0.1uf, 6V3  [402]
C36  0.1uf, 6V3  [402]
C155  0.1uf, 6V3  [402]
FB7  150OHM800mA  [SM-7351-IND-0805]
FB8  0.1 Ohm, 0805  [SM-7351-IND-0805]
J1  Header 3  [HDR1X3]
P4  mini USB-B  [USB5MINI_4SHIELDED_SMD-5]
R26  4.75K, 1%  [R0402]
R27  0R, 1%  [R0402]
R28  33, 0402  [R0402]
R45  33, 0402  [R0402]
R46  33, 0402  [R0402]
R47  33, 0402  [R0402]
R48  33, 0402  [R0402]
R49  0R, 1%  [R0402]
R50  0R, 1%  [R0402]
R51  0R, 1%  [R0402]
R52  10k, 1%  [R0402]
R53  10k, 1%  [R0402]
R159  0R, 1%  [R0402]
R163  4.75K, 1%  [R0402]
R164  4.75K, 1%  [R0402]
R165  100K, 1%  [R0402]
U5  IC_AM335X_ZCE_1  [am33xx_15x15]  (part B of 3)
U8  TPS2051 (DGN)  [DGN-16X60/TPS2051BDGN/8-MSOP]
U9  TPD4S012  [U_6_DRY/TPD4S012DRYR/6-SON]
U10  TPD4S012  [U_6_DRY/TPD4S012DRYR/6-SON]
U15  SN74LVC2G241,DNI  [U_8_DCU/SN74LVC2G241DCUR/US8]

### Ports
AIN0, AIN1, AIN2, AIN3, AIN4, AIN5, AIN6, GPIO0_7, GPIO3_19, GPIO3_20, GPIO3_21, I2C0_SCL, I2C0_SDA, I2C1_SCL, I2C1_SDA, I2C2_SCL, I2C2_SDA, LCD_DATA0, LCD_DATA1, LCD_DATA2, LCD_DATA3, LCD_DATA4, LCD_DATA5, LCD_DATA6, LCD_DATA7, LCD_DATA8, LCD_DATA9, LCD_DATA10, LCD_DATA11, LCD_DATA12, LCD_DATA13, LCD_DATA14, LCD_DATA15, LCD_DE, LCD_HSYNC, LCD_PCLK, LCD_VSYNC, MDIO_CLK, MDIO_DATA, MII1_COL, MII1_CRS_DV, MII1_REFCLK, MII1_RXCLK, MII1_RXD0, MII1_RXD1, MII1_RXD2, MII1_RXD3, MII1_RXDV, MII1_RXERR, MII1_TXCLK, MII1_TXD0, MII1_TXD1, MII1_TXD2, MII1_TXD3, MII1_TXEN, MMC0_CD, PMIC_POWR_EN, SPI1_CS0, SPI1_D0, SPI1_D1, SPI1_SCLK, UART0_RXD, UART0_TXD, UART1_RXD, UART1_TXD, UART2_RXD, UART2_TXD, UART4_RXD, UART4_TXD, USB1_OCn, WAKEUP

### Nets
DGND: C34.2 C35.2 C36.2 C155.1 J1.3 P4.5(G1) R49.1 R53.2(P2) R164.2 R165.2 U8.1(GND) U8.9(PAD) U9.4(GND) U10.4(GND) U15.1(~{1OE}) U15.4(GND)
GND_EARTH: P4.6(G3) P4.7(G2) P4.8(G5) P4.9(G4)
GNDA_ADC: C31.2 C32.2 C33.2 U5.A9(VREFN)
SYS_5V: C34.1 U8.2(IN) U8.3(IN)
USB_DC: C36.1 P4.1(VB) R159.1 U10.6(VBUS)
VDD_3V3A: R52.1(P1)
VDD_3V3B: C155.2 R163.1 U15.7(~{2OE}) U15.8(VCC)
VDD_ADC: R27.1
VRTC: R26.1
AIN0: U5.B6(AIN0) ; port AIN0
AIN1: U5.C7(AIN1) ; port AIN1
AIN2: U5.B7(AIN2) ; port AIN2
AIN3: U5.A7(AIN3) ; port AIN3
AIN4: U5.C8(AIN4) ; port AIN4
AIN5: U5.B8(AIN5) ; port AIN5
AIN6: U5.A8(AIN6) ; port AIN6
AIN7: R163.2 R164.1 U5.C9(AIN7)
B_UART0_RX: J1.2 R165.1 U15.2(1A)
B_UART0_TX: J1.1 U15.3(2Y)
GPIO0_7: R50.1 R51.1 ; port GPIO0_7
GPIO0_7SRC: R50.2 U5.C18(ECAP0_IN_PWM0_OUT/UART3_TXD/SPI1_CS1/PR1_ECAP0_ECAP_CAPIN_APWM_O/SPI1_SCLK/MMC0_SDWP/XDMA_EVENT_INTR2/GPIO0_7)
GPIO3_18: R51.2 U5.B12(MCASP0_ACLKR/EQEP0A_IN/MCASP0_AXR2/MCASP1_ACLKX/MMC0_SDWP/PR1_PRU0_PRU_R30_4/PR1_PRU0_PRU_R31_4/GPIO3_18)
GPIO3_19: U5.C13(MCASP0_FSR/EQEP0B_IN/MCASP0_AXR3/MCASP1_FSX/EMU2/PR1_PRU0_PRU_R30_5/PR1_PRU0_PRU_R31_5/GPIO3_19) ; port GPIO3_19
GPIO3_20: U5.D13(MCASP0_AXR1/EQEP0_INDEX//MCASP1_AXR0/EMU3/PR1_PRU0_PRU_R30_6/PR1_PRU0_PRU_R31_6/GPIO3_20) ; port GPIO3_20
GPIO3_21: U5.A14(MCASP0_AHCLKX/EQEP0_STROBE/MCASP0_AXR3/MCASP1_AXR1/EMU4/PR1_PRU0_PRU_R30_7/PR1_PRU0_PRU_R31_7/GPIO3_21) ; port GPIO3_21
I2C0_SCL: U5.C16(I2C0_SCL/TIMER7/UART2_RTSN/ECAP1_IN_PWM1_OUT////GPIO3_6) ; port I2C0_SCL
I2C0_SDA: U5.C17(I2C0_SDA/TIMER4/UART2_CTSN/ECAP2_IN_PWM2_OUT////GPIO3_5) ; port I2C0_SDA
I2C1_SCL: U5.A16(SPI0_CS0/MMC2_SDWP/I2C1_SCL/EHRPWM0_SYNCI_O/PR1_UART0_TXD/PR1_EDIO_DATA_IN1/PR1_EDIO_DATA_OUT1/GPIO0_5) ; port I2C1_SCL
I2C1_SDA: U5.B16(SPI0_D1/MMC1_SDWP/I2C1_SDA/EHRPWM0_TRIPZONE_INPUT/PR1_UART0_RXD/PR1_EDIO_DATA_IN0/PR1_EDIO_DATA_OUT0/GPIO0_4) ; port I2C1_SDA
I2C2_SCL: U5.D17(UART1_RTSN/TIMER5/DCAN0_RX/I2C2_SCL/SPI1_CS1/PR1_UART0_RTS_N/PR1_EDC_LATCH1_IN/GPIO0_13) ; port I2C2_SCL
I2C2_SDA: U5.D18(UART1_CTSN/TIMER6/DCAN0_TX/I2C2_SDA/SPI1_CS0/PR1_UART0_CTS_N/PR1_EDC_LATCH0_IN/GPIO0_12) ; port I2C2_SDA
LCD_DATA0: U5.R1(LCD_DATA0/GPMC_A0//EHRPWM2A//PR1_PRU1_PRU_R30_0/PR1_PRU1_PRU_R31_0/GPIO2_6) ; port LCD_DATA0
LCD_DATA1: U5.R2(LCD_DATA1/GPMC_A1//EHRPWM2B//PR1_PRU1_PRU_R30_1/PR1_PRU1_PRU_R31_1/GPIO2_7) ; port LCD_DATA1
LCD_DATA2: U5.R3(LCD_DATA2/GPMC_A2//EHRPWM2_TRIPZONE_INPUT//PR1_PRU1_PRU_R30_2/PR1_PRU1_PRU_R31_2/GPIO2_8) ; port LCD_DATA2
LCD_DATA3: U5.R4(LCD_DATA3/GPMC_A3//EHRPWM2_SYNCI_O//PR1_PRU1_PRU_R30_3/PR1_PRU1_PRU_R31_3/GPIO2_9) ; port LCD_DATA3
LCD_DATA4: U5.T1(LCD_DATA4/GPMC_A4//EQEP2A_IN//PR1_PRU1_PRU_R30_4/PR1_PRU1_PRU_R31_4/GPIO2_10) ; port LCD_DATA4
LCD_DATA5: U5.T2(LCD_DATA5/GPMC_A5//EQEP2B_IN//PR1_PRU1_PRU_R30_5/PR1_PRU1_PRU_R31_5/GPIO2_11) ; port LCD_DATA5
LCD_DATA6: U5.T3(LCD_DATA6/GPMC_A6/PR1_EDIO_DATA_IN6/EQEP2_INDEX/PR1_EDIO_DATA_OUT6/PR1_PRU1_PRU_R30_6/PR1_PRU1_PRU_R31_6/GPIO2_12) ; port LCD_DATA6
LCD_DATA7: U5.T4(LCD_DATA7/GPMC_A7/PR1_EDIO_DATA_IN7/EQEP2_STROBE/PR1_EDIO_DATA_OUT7/PR1_PRU1_PRU_R30_7/PR1_PRU1_PRU_R31_7/GPIO2_13) ; port LCD_DATA7
LCD_DATA8: U5.U1(LCD_DATA8/GPMC_A12/EHRPWM1_TRIPZONE_INPUT/MCASP0_ACLKX/UART5_TXD/PR1_MII0_RXD3/UART2_CTSN/GPIO2_14) ; port LCD_DATA8
LCD_DATA9: U5.U2(LCD_DATA9/GPMC_A13/EHRPWM1_SYNCI_O/MCASP0_FSX/UART5_RXD/PR1_MII0_RXD2/UART2_RTSN/GPIO2_15) ; port LCD_DATA9
LCD_DATA10: U5.U3(LCD_DATA10/GPMC_A14/EHRPWM1A/MCASP0_AXR0//PR1_MII0_RXD1/UART3_CTSN/GPIO2_16) ; port LCD_DATA10
LCD_DATA11: U5.U4(LCD_DATA11/GPMC_A15/EHRPWM1B/MCASP0_AHCLKR/MCASP0_AXR2/PR1_MII0_RXD0/UART3_RTSN/GPIO2_17) ; port LCD_DATA11
LCD_DATA12: U5.V2(LCD_DATA12/GPMC_A16/EQEP1A_IN/MCASP0_ACLKR/MCASP0_AXR2/PR1_MII0_RXLINK/UART4_CTSN/GPIO0_8) ; port LCD_DATA12
LCD_DATA13: U5.V3(LCD_DATA13/GPMC_A17/EQEP1B_IN/MCASP0_FSR/MCASP0_AXR3/PR1_MII0_RXER/UART4_RTSN/GPIO0_9) ; port LCD_DATA13
LCD_DATA14: U5.V4(LCD_DATA14/GPMC_A18/EQEP1_INDEX/MCASP0_AXR1/UART5_RXD/PR1_MII_MR0_CLK/UART5_CTSN/GPIO0_10) ; port LCD_DATA14
LCD_DATA15: U5.T5(LCD_DATA15/GPMC_A19/EQEP1_STROBE/MCASP0_AHCLKX/MCASP0_AXR3/PR1_MII0_RXDV/UART5_RTSN/GPIO0_11) ; port LCD_DATA15
LCD_DE: R48.2 ; port LCD_DE
LCD_HSYNC: R47.2 ; port LCD_HSYNC
LCD_PCLK: R45.2 ; port LCD_PCLK
LCD_VSYNC: R46.2 ; port LCD_VSYNC
LCDDE: R48.1 U5.R6(LCD_AC_BIAS_EN/GPMC_A11//PR1_EDIO_DATA_IN5/PR1_EDIO_DATA_OUT5/PR1_PRU1_PRU_R30_11/PR1_PRU1_PRU_R31_11/GPIO2_25)
LCDPCLK: R45.1 U5.V5(LCD_PCLK/GPMC_A10//PR1_EDIO_DATA_IN4/PR1_EDIO_DATA_OUT4/PR1_PRU1_PRU_R30_10/PR1_PRU1_PRU_R31_10/GPIO2_24)
LCDVHYNC: R47.1 U5.R5(LCD_HSYNC/GPMC_A9//PR1_EDIO_DATA_IN3/PR1_EDIO_DATA_OUT3/PR1_PRU1_PRU_R30_9/PR1_PRU1_PRU_R31_9/GPIO2_23)
LCDVSYNC: R46.1 U5.U5(LCD_VSYNC/GPMC_A8//PR1_EDIO_DATA_IN2/PR1_EDIO_DATA_OUT2/PR1_PRU1_PRU_R30_8/PR1_PRU1_PRU_R31_8/GPIO2_22)
MDIO_CLK: U5.M18(MDIO_CLK/TIMER5/UART5_TXD/UART3_RTSN/MMC0_SDWP/MMC1_CLK/MMC2_CLK/GPIO0_1) ; port MDIO_CLK
MDIO_DATA: U5.M17(MDIO_DATA/TIMER6/UART5_RXD/UART3_CTSN/MMC0_SDCD/MMC1_CMD/MMC2_CMD/GPIO0_0) ; port MDIO_DATA
MII1_COL: U5.H16(GMII1_COL/RMII2_REFCLK/SPI1_SCLK/UART5_RXD/MCASP1_AXR2/MMC2_DAT3/MCASP0_AXR2/GPIO3_0) ; port MII1_COL
MII1_CRS_DV: U5.H17(GMII1_CRS/RMII1_CRS_DV/SPI1_D0/I2C1_SDA/MCASP1_ACLKX/UART5_CTSN/UART2_RXD/GPIO3_1) ; port MII1_CRS_DV
MII1_REFCLK: R28.2 ; port MII1_REFCLK
MII1_RXCLK: U5.L18(GMII1_RXCLK/UART2_TXD/RGMII1_RCLK/MMC0_DAT6/MMC1_DAT1/UART1_DSRN/MCASP0_FSX/GPIO3_10) ; port MII1_RXCLK
MII1_RXD0: U5.M16(GMII1_RXD0/RMII1_RXD0/RGMII1_RD0/MCASP1_AHCLKX/MCASP1_AHCLKR/MCASP1_ACLKR/MCASP0_AXR3/GPIO2_21) ; port MII1_RXD0
MII1_RXD1: U5.L15(GMII1_RXD1/RMII1_RXD1/RGMII1_RD1/MCASP1_AXR3/MCASP1_FSR/EQEP0_STROBE/MMC2_CLK/GPIO2_20) ; port MII1_RXD1
MII1_RXD2: U5.L16(GMII1_RXD2/UART3_TXD/RGMII1_RD2/MMC0_DAT4/MMC1_DAT3/UART1_RIN/MCASP0_AXR1/GPIO2_19) ; port MII1_RXD2
MII1_RXD3: U5.L17(GMII1_RXD3/UART3_RXD/RGMII1_RD3/MMC0_DAT5/MMC1_DAT2/UART1_DTRN/MCASP0_AXR0/GPIO2_18) ; port MII1_RXD3
MII1_RXDV: U5.J17(GMII1_RXDV/LCD_MEMORY_CLK/RGMII1_RCTL/UART5_TXD/MCASP1_ACLKX/MMC2_DAT0/MCASP0_ACLKR/GPIO3_4) ; port MII1_RXDV
MII1_RXERR: U5.J15(GMII1_RXERR/RMII1_RXERR/SPI1_D1/I2C1_SCL/MCASP1_FSX/UART5_RTSN/UART2_TXD/GPIO3_2) ; port MII1_RXERR
MII1_TXCLK: U5.K18(GMII1_TXCLK/UART2_RXD/RGMII1_TCLK/MMC0_DAT7/MMC1_DAT0/UART1_DCDN/MCASP0_ACLKX/GPIO3_9) ; port MII1_TXCLK
MII1_TXD0: U5.K17(GMII1_TXD0/RMII1_TXD0/RGMII1_TD0/MCASP1_AXR2/MCASP1_ACLKR/EQEP0B_IN/MMC1_CLK/GPIO0_28) ; port MII1_TXD0
MII1_TXD1: U5.K16(GMII1_TXD1/RMII1_TXD1/RGMII1_TD1/MCASP1_FSR/MCASP1_AXR1/EQEP0A_IN/MMC1_CMD/GPIO0_21) ; port MII1_TXD1
MII1_TXD2: U5.K15(GMII1_TXD2/DCAN0_RX/RGMII1_TD2/UART4_TXD/MCASP1_AXR0/MMC2_DAT2/MCASP0_AHCLKX/GPIO0_17) ; port MII1_TXD2
MII1_TXD3: U5.J18(GMII1_TXD3/DCAN0_TX/RGMII1_TD3/UART4_RXD/MCASP1_FSX/MMC2_DAT1/MCASP0_FSR/GPIO0_16) ; port MII1_TXD3
MII1_TXEN: U5.J16(GMII1_TXEN/RMII1_TXEN/RGMII1_TCTL/TIMER4/MCASP1_AXR0/EQEP0_INDEX/MMC2_CMD/GPIO3_3) ; port MII1_TXEN
MMC0_CD: U5.C15(SPI0_CS1/UART3_RXD/ECAP1_IN_PWM1_OUT/MMC0_POW/XDMA_EVENT_INTR2/MMC0_SDCD/EMU4/GPIO0_6) ; port MMC0_CD
PMIC_POWR_EN: U5.C6(PMIC_POWER_EN) ; port PMIC_POWR_EN
SPI1_CS0: U5.C12(MCASP0_AHCLKR/EHRPWM0_SYNCI_O/MCASP0_AXR2/SPI1_CS0/ECAP2_IN_PWM2_OUT/PR1_PRU0_PRU_R30_3/PR1_PRU0_PRU_R31_3/GPIO3_17) ; port SPI1_CS0
SPI1_D0: U5.B13(MCASP0_FSX/EHRPWM0B//SPI1_D0/MMC1_SDCD/PR1_PRU0_PRU_R30_1/PR1_PRU0_PRU_R31_1/GPIO3_15) ; port SPI1_D0
SPI1_D1: U5.D12(MCASP0_AXR0/EHRPWM0_TRIPZONE_INPUT//SPI1_D1/MMC2_SDCD/PR1_PRU0_PRU_R30_2/PR1_PRU0_PRU_R31_2/GPIO3_16) ; port SPI1_D1
SPI1_SCLK: U5.A13(MCASP0_ACLKX/EHRPWM0A//SPI1_SCLK/MMC0_SDCD/PR1_PRU0_PRU_R30_0/PR1_PRU0_PRU_R31_0/GPIO3_14) ; port SPI1_SCLK
U5_H18: R28.1 U5.H18(RMII1_REFCLK/XDMA_EVENT_INTR2/SPI1_CS0/UART5_TXD/MCASP1_AXR3/MMC0_POW/MCASP1_AHCLKX/GPIO0_29)
UART0_RXD: U5.E15(UART0_RXD/SPI1_CS0/DCAN0_TX/I2C2_SDA/ECAP2_IN_PWM2_OUT/PR1_PRU1_PRU_R30_14/PR1_PRU1_PRU_R31_14/GPIO1_10) U15.6(1Y) ; port UART0_RXD
UART0_TXD: U5.E16(UART0_TXD/SPI1_CS1/DCAN0_RX/I2C2_SCL/ECAP1_IN_PWM1_OUT/PR1_PRU1_PRU_R30_15/PR1_PRU1_PRU_R31_15/GPIO1_11) U15.5(2A) ; port UART0_TXD
UART1_RXD: U5.D16(UART1_RXD/MMC1_SDWP/DCAN1_TX/I2C1_SDA//PR1_UART0_RXD/PR1_PRU1_PRU_R31_16/GPIO0_14) ; port UART1_RXD
UART1_TXD: U5.D15(UART1_TXD/MMC2_SDWP/DCAN1_RX/I2C1_SCL//PR1_UART0_TXD/PR1_PRU0_PRU_R31_16/GPIO0_15) ; port UART1_TXD
UART2_RXD: U5.A17(SPI0_SCLK/UART2_RXD/I2C2_SDA/EHRPWM0A/PR1_UART0_CTS_N/PR1_EDIO_SOF/EMU2/GPIO0_2) ; port UART2_RXD
UART2_TXD: U5.B17(SPI0_D0/UART2_TXD/I2C2_SCL/EHRPWM0B/PR1_UART0_RTS_N/PR1_EDIO_LATCH_IN/EMU3/GPIO0_3) ; port UART2_TXD
UART4_RXD: U5.E18(UART0_CTSN/UART4_RXD/DCAN1_TX/I2C1_SDA/SPI1_D0/TIMER7/PR1_EDC_SYNC0_OUT/GPIO1_8) ; port UART4_RXD
UART4_TXD: U5.E17(UART0_RTSN/UART4_TXD/DCAN1_RX/I2C1_SCL/SPI1_D1/SPI1_CS0/PR1_EDC_SYNC1_OUT/GPIO1_9) ; port UART4_TXD
USB0_DM: P4.2(D-) U5.N18(USB0_DM) U10.2(D-)
USB0_DP: P4.3(D+) U5.N17(USB0_DP) U10.1(D+)
USB0_ID: P4.4(ID) U5.P16(USB0_ID) U10.3(ID)
USB1_DM: U5.R18(USB1_DM) U9.2(D-)
USB1_DP: U5.R17(USB1_DP) U9.1(D+)
USB1_DRVVBUS: R53.1(P1) U5.F15(USB1_DRVVBUS/GPIO3_13) U8.4(EN)
USB1_ID: R49.2 U5.P17(USB1_ID)
USB1_OCn: R52.2(P2) U8.5(~{OC}) ; port USB1_OCn
USB1_PWR: C35.1 FB7.1 FB8.2 U8.6(OUT) U8.7(OUT) U8.8(OUT) U9.6(VBUS)
USB1_VBUS: FB8.1 U5.T18(USB1_VBUS)
VBUS: FB7.2
VREFP_ADC: C31.1 C32.1 C33.1 R27.2 U5.B9(VREFP)
WAKEUP: R26.2 U5.C5(EXT_WAKEUP) ; port WAKEUP
NetR159_2: R159.2 U5.P15(USB0_VBUS)

Not connected (* = marked no-connect by the designer): U5 F16(USB0_DRVVBUS/GPIO0_18)* M15(USB0_CE)* P18(USB1_CE)*; U9 3(ID) 5(NC)*; U10 5(NC)

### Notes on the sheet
- 模拟信号，注意走线！
  AIN0AIN6
- (near R159) USB0用90欧姆差分线！
- USB1用90欧姆差分线！
- CONNECTOR
- USB PC

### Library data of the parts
C31 C33 C35 C36 C155 = CAP_0.1uF_X7R_16V_10% 0402: as C20 on sheet P02_PowerManagement
C32 = CAP_0.001_X7R_50V_5%_0402: CAP CER 1000PF 16V 10% X7R 0402; Manufacturer: Yageo; Manufacturer Part Number: CC0402KRX7R7BB102; Tolerance: ?0%
C34 = CAPACITOR POL: Capacitor
FB7 = FER_180_200_0: FERRITE 800MA 150 OHM 0805 SMD; PartName: FerriteBead150ohm800mA; Mfr: Steward; MfrNum: LI0805H151R-10; TIIntPartnumber: 1L0010; Manufacturer: Laird-Signal Integrity Products; Vendor: Digikey; Impedance @ Frequency: 150 Ohm @ 100MHz; DC Resistance (DCR): 150 mOhm Max; Filter Type: Differential Mode - Single
FB8 = FER_180_200_0: as FB10 on sheet P02_PowerManagement
J1 = Header 3: Header, 3-Pin
P4 = MINI-USB-AB-SOCKET: CONN RCPT USB MINI B R/A SMD; Manufacturer: KYCON; Manufacturer Part Number: 0565790576; Order# 2: C-440247; ATLStockNo1: 4500.0223; Order#: KMAB-SMT-5S-S-30TR; Connector Type: USB - mini AB; Number of Contacts: 5; Gender: Receptacle; Specifications: USB 2.0 OTG
R26 R163 R164 = RES_4.75K_1/16W_1%_0402: RES 4.75K OHM 1/16W 1% 0402 SMD; Manufacturer: Stackpole Electronics Inc; Manufacturer Part Number: RMCF0402FT4K75; Power (Watts): 0.063W, 1/16W; Temperature Coefficient: ?00ppm/°C; Tolerance: ?%
R27 = RES_0_1/16W_1%_0402: as R19 on sheet P03_Processor1_3
R28 R45-R48 = RES_33_0402: as R18 on sheet P03_Processor1_3
R49-R51 R159 = RES_0_1/16W_1%_0402: as R5 on sheet P02_PowerManagement
R52 R53 = RES SMD: RES 10K OHM 1/16W 5% 0402 SMD; Manufacturer: Rohm Semiconductor; Manufacturer Part Number: MCR01MZPJ103; Power (Watts): 0.063W, 1/16W; Temperature Coefficient: ?00ppm/°C; Tolerance: ?%
R165 = RES_100K_1/16W_1%_0402: as R1 on sheet P02_PowerManagement
U5 = IC_AM335X_ZCE_1: SubArctic Cortex A8 Processor 15x15; PartName: AM335X_15x15; Mfr: TI; MfrNum: AM335x 15x15 FBGA ZCE; TIIntPartnumber: 1A0242; Manufacturer: Texas Instruments; Manufacturer Part Number: XAM3359ZCZ; Vendor: Arrow; Cost100: 10.00; Processor Type: ARM Microprocessor; Voltage: 1.06 V ~ 1.15 V
U8 = TPS2061_0: IC 1.5A PWR DIST SWITCH 8-SOIC; Manufacturer: Texas Instruments; Manufacturer Part Number: TPS2051BDGNR; Number of Outputs: 1; Rds (On): 135 mOhm; Internal Switch(s): Yes; Current Limit: 1A; Voltage - Input: 2.7 V ~ 5.5 V
U9 U10 = PROT_TPD4S012: ESD 4channel USB Interface; Mfr: TI; MfrNum: TPD4S012DRY; TIIntPartnumber: 1A0233; Manufacturer: Texas Instruments; Manufacturer Part Number: TPD4S012DRYR; Vendor: Digikey; Cost100: 0.76; Cost10K: 0.23; Power (Watts): 60W; Number of Circuits: 4
U15 = SN74LVC2G241: IC BUFF/DVR TRI-ST DL 8VSSOP; Manufacturer: Texas Instruments; Manufacturer Part Number: SN74LVC2G241DCUR; Logic Type: Buffer/Line Driver, Non-Inverting; Number of Elements: 2; Number of Bits per Element: 1; Current - Output High, Low: 32mA, 32mA; Voltage - Supply: 1.65 V ~ 5.5 V

## Sheet P05_Processor3_3.SchDoc
size A2
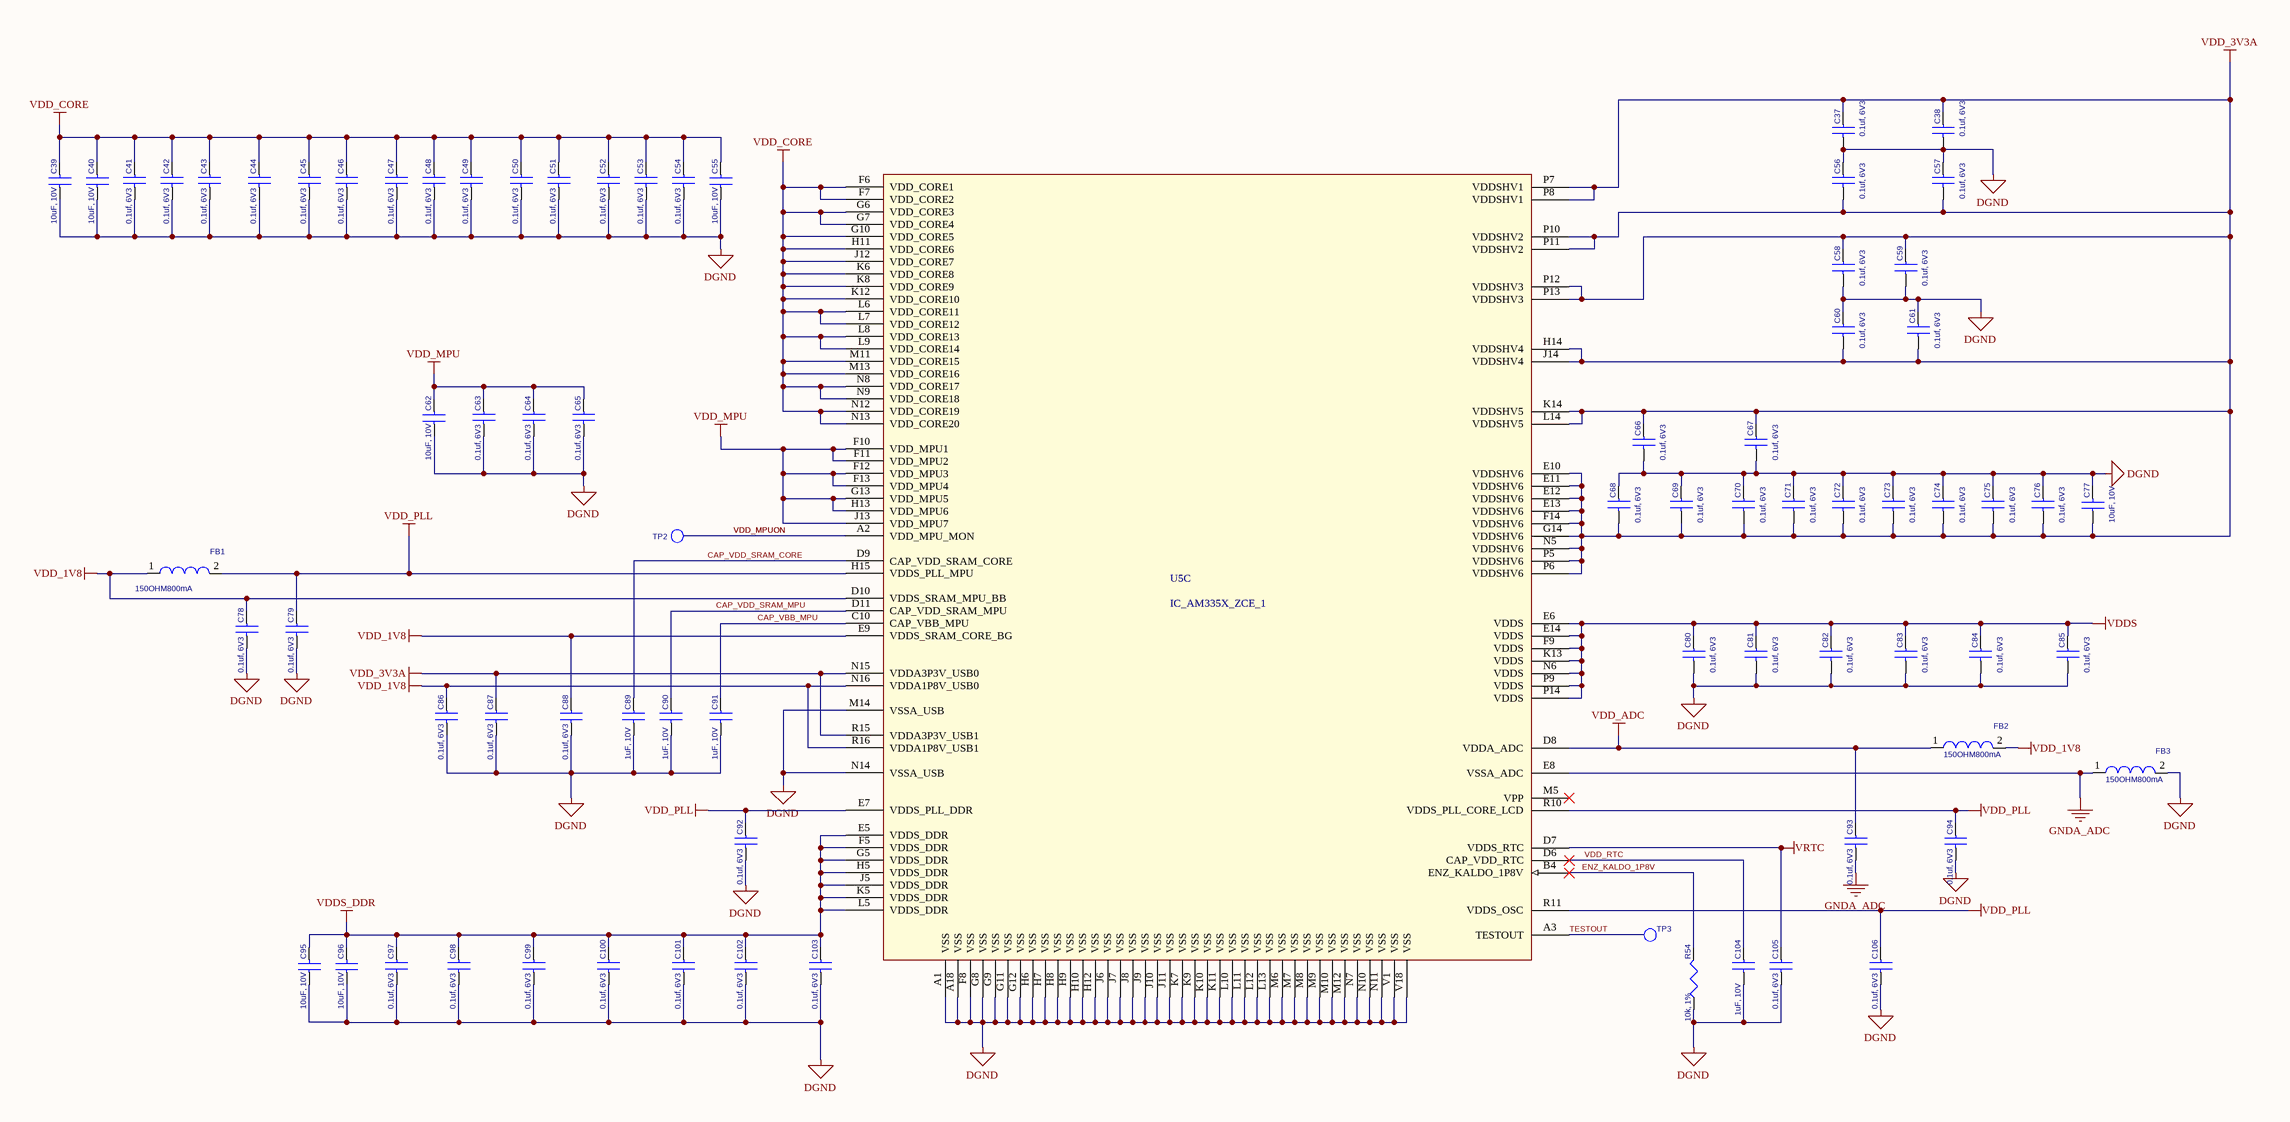
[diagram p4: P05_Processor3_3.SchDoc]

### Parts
C37  0.1uf, 6V3  [402]
C38  0.1uf, 6V3  [402]
C39  10uF, 10V  [805]
C40  10uF, 10V  [805]
C41  0.1uf, 6V3  [402]
C42  0.1uf, 6V3  [402]
C43  0.1uf, 6V3  [402]
C44  0.1uf, 6V3  [402]
C45  0.1uf, 6V3  [402]
C46  0.1uf, 6V3  [402]
C47  0.1uf, 6V3  [402]
C48  0.1uf, 6V3  [402]
C49  0.1uf, 6V3  [402]
C50  0.1uf, 6V3  [402]
C51  0.1uf, 6V3  [402]
C52  0.1uf, 6V3  [402]
C53  0.1uf, 6V3  [402]
C54  0.1uf, 6V3  [402]
C55  10uF, 10V  [805]
C56  0.1uf, 6V3  [402]
C57  0.1uf, 6V3  [402]
C58  0.1uf, 6V3  [402]
C59  0.1uf, 6V3  [402]
C60  0.1uf, 6V3  [402]
C61  0.1uf, 6V3  [402]
C62  10uF, 10V  [805]
C63  0.1uf, 6V3  [402]
C64  0.1uf, 6V3  [402]
C65  0.1uf, 6V3  [402]
C66  0.1uf, 6V3  [402]
C67  0.1uf, 6V3  [402]
C68  0.1uf, 6V3  [402]
C69  0.1uf, 6V3  [402]
C70  0.1uf, 6V3  [402]
C71  0.1uf, 6V3  [402]
C72  0.1uf, 6V3  [402]
C73  0.1uf, 6V3  [402]
C74  0.1uf, 6V3  [402]
C75  0.1uf, 6V3  [402]
C76  0.1uf, 6V3  [402]
C77  10uF, 10V  [805]
C78  0.1uf, 6V3  [402]
C79  0.1uf, 6V3  [402]
C80  0.1uf, 6V3  [402]
C81  0.1uf, 6V3  [402]
C82  0.1uf, 6V3  [402]
C83  0.1uf, 6V3  [402]
C84  0.1uf, 6V3  [402]
C85  0.1uf, 6V3  [402]
C86  0.1uf, 6V3  [402]
C87  0.1uf, 6V3  [402]
C88  0.1uf, 6V3  [402]
C89  1uF, 10V  [402]
C90  1uF, 10V  [402]
C91  1uF, 10V  [402]
C92  0.1uf, 6V3  [402]
C93  0.1uf, 6V3  [402]
C94  0.1uf, 6V3  [402]
C95  10uF, 10V  [805]
C96  10uF, 10V  [805]
C97  0.1uf, 6V3  [402]
C98  0.1uf, 6V3  [402]
C99  0.1uf, 6V3  [402]
C100  0.1uf, 6V3  [402]
C101  0.1uf, 6V3  [402]
C102  0.1uf, 6V3  [402]
C103  0.1uf, 6V3  [402]
C104  1uF, 10V  [402]
C105  0.1uf, 6V3  [402]
C106  0.1uf, 6V3  [402]
FB1  150OHM800mA  [SM-7351-IND-0805]
FB2  150OHM800mA  [SM-7351-IND-0805]
FB3  150OHM800mA  [SM-7351-IND-0805]
R54  10k, 1%  [R0402]
TP2  TESTPT1  [TP60C_SMD]  (value not drawn)  (no BOM)
TP3  TESTPT1  [TP60C_SMD]  (value not drawn)  (no BOM)
U5  IC_AM335X_ZCE_1  [am33xx_15x15]  (part C of 3)

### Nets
DGND: C37.2 C38.2 C39.1 C40.1 C41.2 C42.2 C43.2 C44.2 C45.2 C46.2 C47.2 C48.2 C49.2 C50.2 C51.2 C52.2 C53.2 C54.2 C55.1 C56.1 C57.1 C58.2 C59.2 C60.1 C61.1 C62.1 C63.2 C64.2 C65.2 C66.2 C67.2 C68.1 C69.1 C70.1 C71.1 C72.1 C73.1 C74.1 C75.1 C76.1 C77.2 C78.2 C79.2 C80.2 C81.2 C82.2 C83.2 C84.2 C85.2 C86.2 C87.2 C88.2 C89.2 C90.2 C91.2 C92.2 C94.2 C95.1 C96.1 C97.2 C98.2 C99.2 C100.2 C101.2 C102.2 C103.2 C104.2 C105.2 C106.2 FB3.2 R54.1 U5.A1(VSS) U5.A18(VSS) U5.F8(VSS) U5.G8(VSS) U5.G9(VSS) U5.G11(VSS) U5.G12(VSS) U5.H6(VSS) U5.H7(VSS) U5.H8(VSS) U5.H9(VSS) U5.H10(VSS) U5.H12(VSS) U5.J6(VSS) U5.J7(VSS) U5.J8(VSS) U5.J9(VSS) U5.J10(VSS) U5.J11(VSS) U5.K7(VSS) U5.K9(VSS) U5.K10(VSS) U5.K11(VSS) U5.L10(VSS) U5.L11(VSS) U5.L12(VSS) U5.L13(VSS) U5.M6(VSS) U5.M7(VSS) U5.M8(VSS) U5.M9(VSS) U5.M10(VSS) U5.M12(VSS) U5.M14(VSSA_USB) U5.N7(VSS) U5.N10(VSS) U5.N11(VSS) U5.N14(VSSA_USB) U5.V1(VSS) U5.V18(VSS)
GNDA_ADC: C93.2 FB3.1 U5.E8(VSSA_ADC)
VDD_1V8: C78.1 C86.1 C88.1 FB1.1 FB2.2 U5.D10(VDDS_SRAM_MPU_BB) U5.E9(VDDS_SRAM_CORE_BG) U5.N16(VDDA1P8V_USB0) U5.R16(VDDA1P8V_USB1)
VDD_3V3A: C37.1 C38.1 C56.2 C57.2 C58.1 C59.1 C60.2 C61.2 C66.1 C67.1 C68.2 C69.2 C70.2 C71.2 C72.2 C73.2 C74.2 C75.2 C76.2 C77.1 C87.1 U5.E10(VDDSHV6) U5.E11(VDDSHV6) U5.E12(VDDSHV6) U5.E13(VDDSHV6) U5.F14(VDDSHV6) U5.G14(VDDSHV6) U5.H14(VDDSHV4) U5.J14(VDDSHV4) U5.K14(VDDSHV5) U5.L14(VDDSHV5) U5.N5(VDDSHV6) U5.N15(VDDA3P3V_USB0) U5.P5(VDDSHV6) U5.P6(VDDSHV6) U5.P7(VDDSHV1) U5.P8(VDDSHV1) U5.P10(VDDSHV2) U5.P11(VDDSHV2) U5.P12(VDDSHV3) U5.P13(VDDSHV3) U5.R15(VDDA3P3V_USB1)
VDD_ADC: C93.1 FB2.1 U5.D8(VDDA_ADC)
VDD_CORE: C39.2 C40.2 C41.1 C42.1 C43.1 C44.1 C45.1 C46.1 C47.1 C48.1 C49.1 C50.1 C51.1 C52.1 C53.1 C54.1 C55.2 U5.F6(VDD_CORE1) U5.F7(VDD_CORE2) U5.G6(VDD_CORE3) U5.G7(VDD_CORE4) U5.G10(VDD_CORE5) U5.H11(VDD_CORE6) U5.J12(VDD_CORE7) U5.K6(VDD_CORE8) U5.K8(VDD_CORE9) U5.K12(VDD_CORE10) U5.L6(VDD_CORE11) U5.L7(VDD_CORE12) U5.L8(VDD_CORE13) U5.L9(VDD_CORE14) U5.M11(VDD_CORE15) U5.M13(VDD_CORE16) U5.N8(VDD_CORE17) U5.N9(VDD_CORE18) U5.N12(VDD_CORE19) U5.N13(VDD_CORE20)
VDD_MPU: C62.2 C63.1 C64.1 C65.1 U5.F10(VDD_MPU1) U5.F11(VDD_MPU2) U5.F12(VDD_MPU3) U5.F13(VDD_MPU4) U5.G13(VDD_MPU5) U5.H13(VDD_MPU6) U5.J13(VDD_MPU7)
VDD_PLL: C79.1 C92.1 C94.1 C106.1 FB1.2 U5.E7(VDDS_PLL_DDR) U5.H15(VDDS_PLL_MPU) U5.R10(VDDS_PLL_CORE_LCD) U5.R11(VDDS_OSC)
VDDS: C80.1 C81.1 C82.1 C83.1 C84.1 C85.1 U5.E6(VDDS) U5.E14(VDDS) U5.F9(VDDS) U5.K13(VDDS) U5.N6(VDDS) U5.P9(VDDS) U5.P14(VDDS)
VDDS_DDR: C95.2 C96.2 C97.1 C98.1 C99.1 C100.1 C101.1 C102.1 C103.1 U5.E5(VDDS_DDR) U5.F5(VDDS_DDR) U5.G5(VDDS_DDR) U5.H5(VDDS_DDR) U5.J5(VDDS_DDR) U5.K5(VDDS_DDR) U5.L5(VDDS_DDR)
VRTC: C105.1 U5.D7(VDDS_RTC)
CAP_VBB_MPU: C91.1 U5.C10(CAP_VBB_MPU)
CAP_VDD_SRAM_CORE: C89.1 U5.D9(CAP_VDD_SRAM_CORE)
CAP_VDD_SRAM_MPU: C90.1 U5.D11(CAP_VDD_SRAM_MPU)
ENZ_KALDO_1P8V: R54.2 U5.B4(ENZ_KALDO_1P8V)
TESTOUT: TP3.1(TP) U5.A3(TESTOUT)
VDD_MPUON: TP2.1(TP) U5.A2(VDD_MPU_MON)
VDD_RTC: C104.1 U5.D6(CAP_VDD_RTC)

Not connected (* = marked no-connect by the designer): U5 M5(VPP)*

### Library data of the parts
C37 C38 C41-C54 C56-C61 C63-C76 C78-C88 C92-C94 C97-C103 C105 C106 = CAP_0.1uF_X7R_16V_10% 0402: as C20 on sheet P02_PowerManagement
C39 C55 C62 C77 C95 C96 = CAP_10uF_Y5V_10V_10%_0805: as C4 on sheet P02_PowerManagement
C40 = CAP_10uF_Y5V_10V_10%_0805: CAP CER 10UF 10V Y5V 0805; Manufacturer: TDK Corporation; Manufacturer Part Number: C2012Y5V1A106Z; Capacitance: 10µF; Temperature Coefficient: Y5V (F); Tolerance: -20%, +80%
C89-C91 C104 = CAP_1.0UF_X5R_10V_10%_0402: as C24 on sheet P03_Processor1_3
FB1-FB3 = FER_180_200_0: as FB7 on sheet P04_Processor2_3
R54 = RES_10K_1/16W_1%_0402: as R14 on sheet P03_Processor1_3
U5 = IC_AM335X_ZCE_1: as U5 on sheet P04_Processor2_3

## Sheet P06_LED_BootConfig.SchDoc
size A3
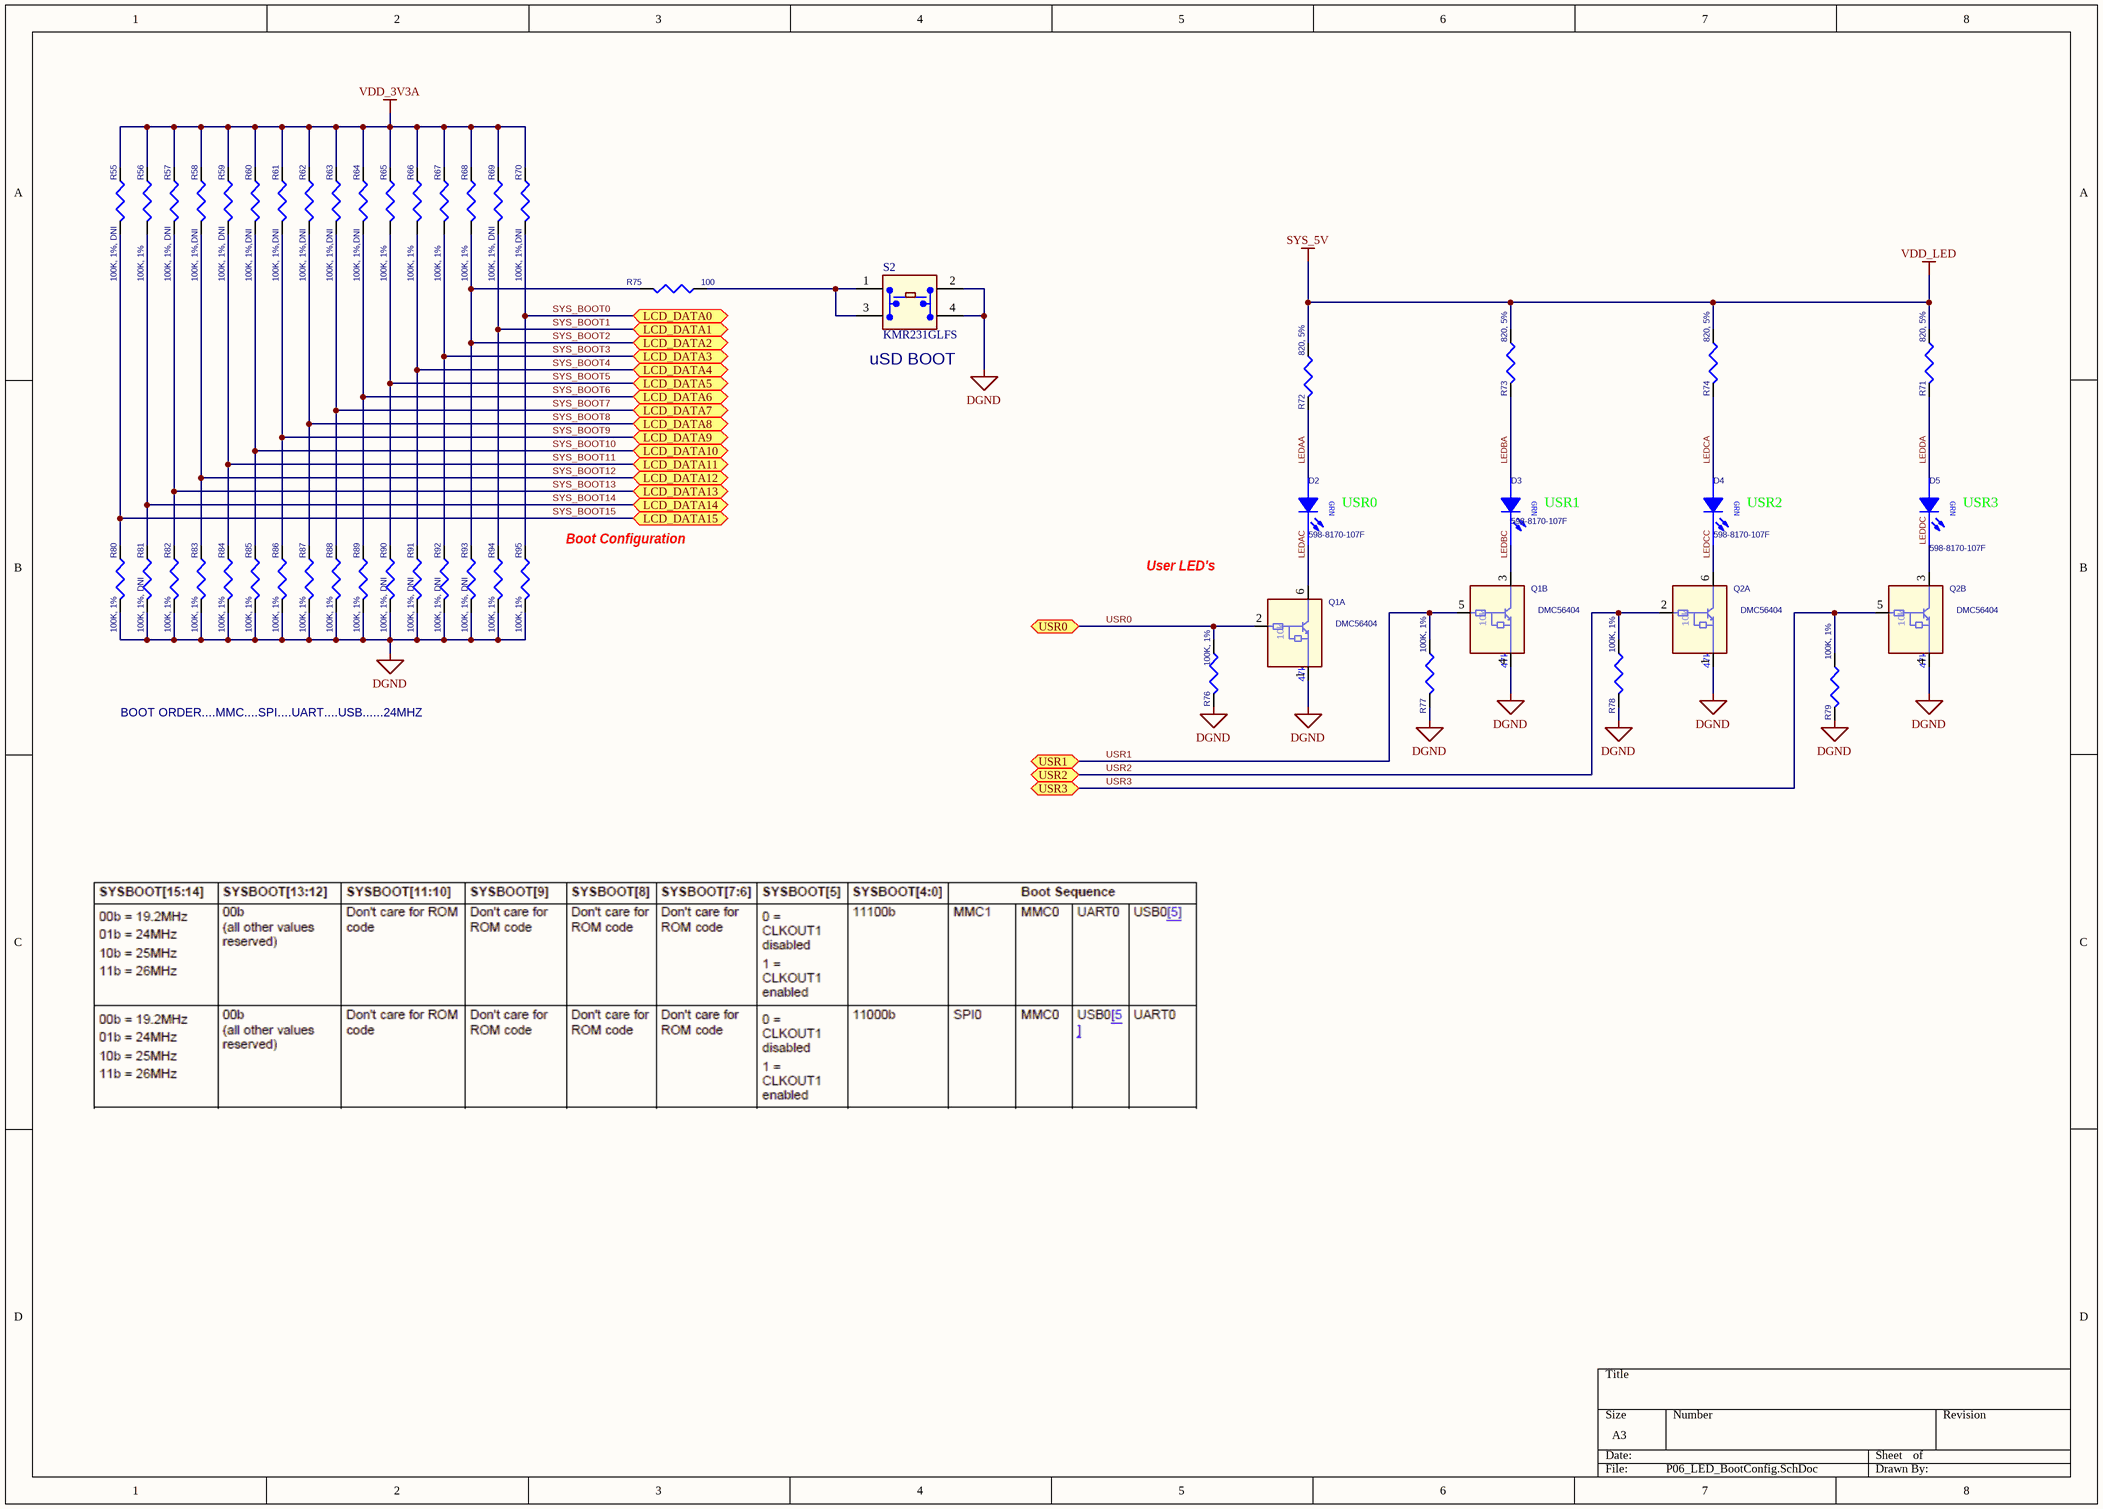
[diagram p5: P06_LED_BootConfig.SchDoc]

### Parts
D2  598-8170-107F  [LED_0603]
D3  598-8170-107F  [LED_0603]
D4  598-8170-107F  [LED_0603]
D5  598-8170-107F  [LED_0603]
Q1  DMC56404  [SMini6-F3-B/DDC114YU-7-F/SOT363]  (parts A,B of 2)
Q2  DMC56404  [SMini6-F3-B]  (parts A,B of 2)
R55  100K, 1%, DNI  [R0402]
R56  100K, 1%  [R0402]
R57  100K, 1%, DNI  [R0402]
R58  100K, 1%,DNI  [R0402]
R59  100K, 1%, DNI  [R0402]
R60  100K, 1%,DNI  [R0402]
R61  100K, 1%,DNI  [R0402]
R62  100K, 1%,DNI  [R0402]
R63  100K, 1%,DNI  [R0402]
R64  100K, 1%,DNI  [R0402]
R65  100K, 1%  [R0402]
R66  100K, 1%  [R0402]
R67  100K, 1%  [R0402]
R68  100K, 1%  [R0402]
R69  100K, 1%, DNI  [R0402]
R70  100K, 1%,DNI  [R0402]
R71  820, 5%  [R0402]
R72  820, 5%  [R0402]
R73  820, 5%  [R0402]
R74  820, 5%  [R0402]
R75  100  [R0402]
R76  100K, 1%  [R0402]
R77  100K, 1%  [R0402]
R78  100K, 1%  [R0402]
R79  100K, 1%  [R0402]
R80  100K, 1%  [R0402]
R81  100K, 1%, DNI  [R0402]
R82  100K, 1%  [R0402]
R83  100K, 1%  [R0402]
R84  100K, 1%  [R0402]
R85  100K, 1%  [R0402]
R86  100K, 1%  [R0402]
R87  100K, 1%  [R0402]
R88  100K, 1%  [R0402]
R89  100K, 1%  [R0402]
R90  100K, 1%, DNI  [R0402]
R91  100K, 1%, DNI  [R0402]
R92  100K, 1%, DNI  [R0402]
R93  100K, 1%, DNI  [R0402]
R94  100K, 1%  [R0402]
R95  100K, 1%  [R0402]
S2  KMR231GLFS  [SW4SMD_63X161LS]

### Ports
LCD_DATA0, LCD_DATA1, LCD_DATA2, LCD_DATA3, LCD_DATA4, LCD_DATA5, LCD_DATA6, LCD_DATA7, LCD_DATA8, LCD_DATA9, LCD_DATA10, LCD_DATA11, LCD_DATA12, LCD_DATA13, LCD_DATA14, LCD_DATA15, USR0, USR1, USR2, USR3

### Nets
DGND: Q1.1 Q1.4 Q2.1 Q2.4 R76.2 R77.2 R78.2 R79.2 R80.2 R81.2 R82.2 R83.2 R84.2 R85.2 R86.2 R87.2 R88.2 R89.2 R90.2 R91.2 R92.2 R93.2 R94.2 R95.2 S2.2(A2) S2.4
SYS_5V: R71.1 R72.1 R73.1 R74.1  [also labelled VDD_LED]
VDD_3V3A: R55.1 R56.1 R57.1 R58.1 R59.1 R60.1 R61.1 R62.1 R63.1 R64.1 R65.1 R66.1 R67.1 R68.1 R69.1 R70.1
LEDAA: D2.2(A) R72.2
LEDAC: D2.1(C) Q1.6
LEDBA: D3.2(A) R73.2
LEDBC: D3.1(C) Q1.3
LEDCA: D4.2(A) R74.2
LEDCC: D4.1(C) Q2.6
LEDDA: D5.2(A) R71.2
LEDDC: D5.1(C) Q2.3
SYS_BOOT0: R70.2 R95.1 ; port LCD_DATA0  [project net LCD_DATA0]
SYS_BOOT1: R69.2 R94.1 ; port LCD_DATA1  [project net LCD_DATA1]
SYS_BOOT2: R68.2 R75.1(P1) R93.1 ; port LCD_DATA2  [project net LCD_DATA2]
SYS_BOOT3: R67.2 R92.1 ; port LCD_DATA3  [project net LCD_DATA3]
SYS_BOOT4: R66.2 R91.1 ; port LCD_DATA4  [project net LCD_DATA4]
SYS_BOOT5: R65.2 R90.1 ; port LCD_DATA5  [project net LCD_DATA5]
SYS_BOOT6: R64.2 R89.1 ; port LCD_DATA6  [project net LCD_DATA6]
SYS_BOOT7: R63.2 R88.1 ; port LCD_DATA7  [project net LCD_DATA7]
SYS_BOOT8: R62.2 R87.1 ; port LCD_DATA8  [project net LCD_DATA8]
SYS_BOOT9: R61.2 R86.1 ; port LCD_DATA9  [project net LCD_DATA9]
SYS_BOOT10: R60.2 R85.1 ; port LCD_DATA10  [project net LCD_DATA10]
SYS_BOOT11: R59.2 R84.1 ; port LCD_DATA11  [project net LCD_DATA11]
SYS_BOOT12: R58.2 R83.1 ; port LCD_DATA12  [project net LCD_DATA12]
SYS_BOOT13: R57.2 R82.1 ; port LCD_DATA13  [project net LCD_DATA13]
SYS_BOOT14: R56.2 R81.1 ; port LCD_DATA14  [project net LCD_DATA14]
SYS_BOOT15: R55.2 R80.1 ; port LCD_DATA15  [project net LCD_DATA15]
USR0: Q1.2 R76.1 ; port USR0
USR1: Q1.5 R77.1 ; port USR1
USR2: Q2.2 R78.1 ; port USR2
USR3: Q2.5 R79.1 ; port USR3
NetR75_2: R75.2(P2) S2.1(A1) S2.3(A3)

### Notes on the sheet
- (near S2) uSD BOOT
- (near D2) USR0
- (near D3) USR1
- (near D4) USR2
- (near D5) USR3
- (near R95) Boot Configuration
- User LED's
- BOOT ORDER....MMC....SPI....UART....USB......24MHZ

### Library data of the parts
D2-D5 = LED_LTST-C150GKT: LED GREEN CLEAR 0805 SMD; Manufacturer: Lite-On Inc; Manufacturer Part Number: LTST-C170KGKT; CLASS: DISCRETE; TN: 257-0020-000; Current - Test: 20mA; Lens Style/Size: Rectangle with Flat Top, 1.4mm x 1.25mm; Millicandela Rating: 35mcd; Viewing Angle: 130; Voltage - Forward (Vf) Typ: 2V; Wavelength - Dominant: 571nm; Wavelength - Peak: 574nm
Q1 Q2 = RN1907: TRANS PREBIASED DUAL NPN SOT363; Manufacturer: Toshiba; Manufacturer Part Number: DDC114YU-7-F; Order# 2: BCR135S; ATLStockNo1: 2130.0137; ATLStockNo2: 2130.01; Transistor Type: 2 NPN - Pre-Biased (Dual); Current - Collector (Ic) (Max): 100mA; Voltage - Collector Emitter Breakdown (Max): 50V; Resistor - Base (R1) (Ohms): 10k; Resistor - Emitter Base (R2) (Ohms): 47k; DC Current Gain (hFE) (Min) @ Ic, Vce: 68 @ 10mA, 5V; Vce Saturation (Max) @ Ib, Ic: 300mV @ 250µA, 5mA; Current - Collector Cutoff (Max): 500nA; Frequency - Transition: 250MHz; Power - Max: 200mW
R55-R70 R76-R95 = RES_100K_1/16W_1%_0402: as R1 on sheet P02_PowerManagement
R71-R74 = RES_470_1/10W_5%_0402: RES 820 OHM 1/10W 5% 0402 SMD; Manufacturer: Yageo; Manufacturer Part Number: RC0402JR-07820RL; Power (Watts): 0.063W, 1/16W; Resistance (Ohms): 820; Temperature Coefficient: ?00ppm/°C; Tolerance: ?%
R75 = RES SMD: RES 100 OHM 1/10W 5% 0402 SMD; Manufacturer: Panasonic Electronic Components; Manufacturer Part Number: ERJ-2RKF1000X; Power (Watts): 0.1W, 1/10W; Temperature Coefficient: ?00ppm/°C
S2 = KMR2: as S3 on sheet P02_PowerManagement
